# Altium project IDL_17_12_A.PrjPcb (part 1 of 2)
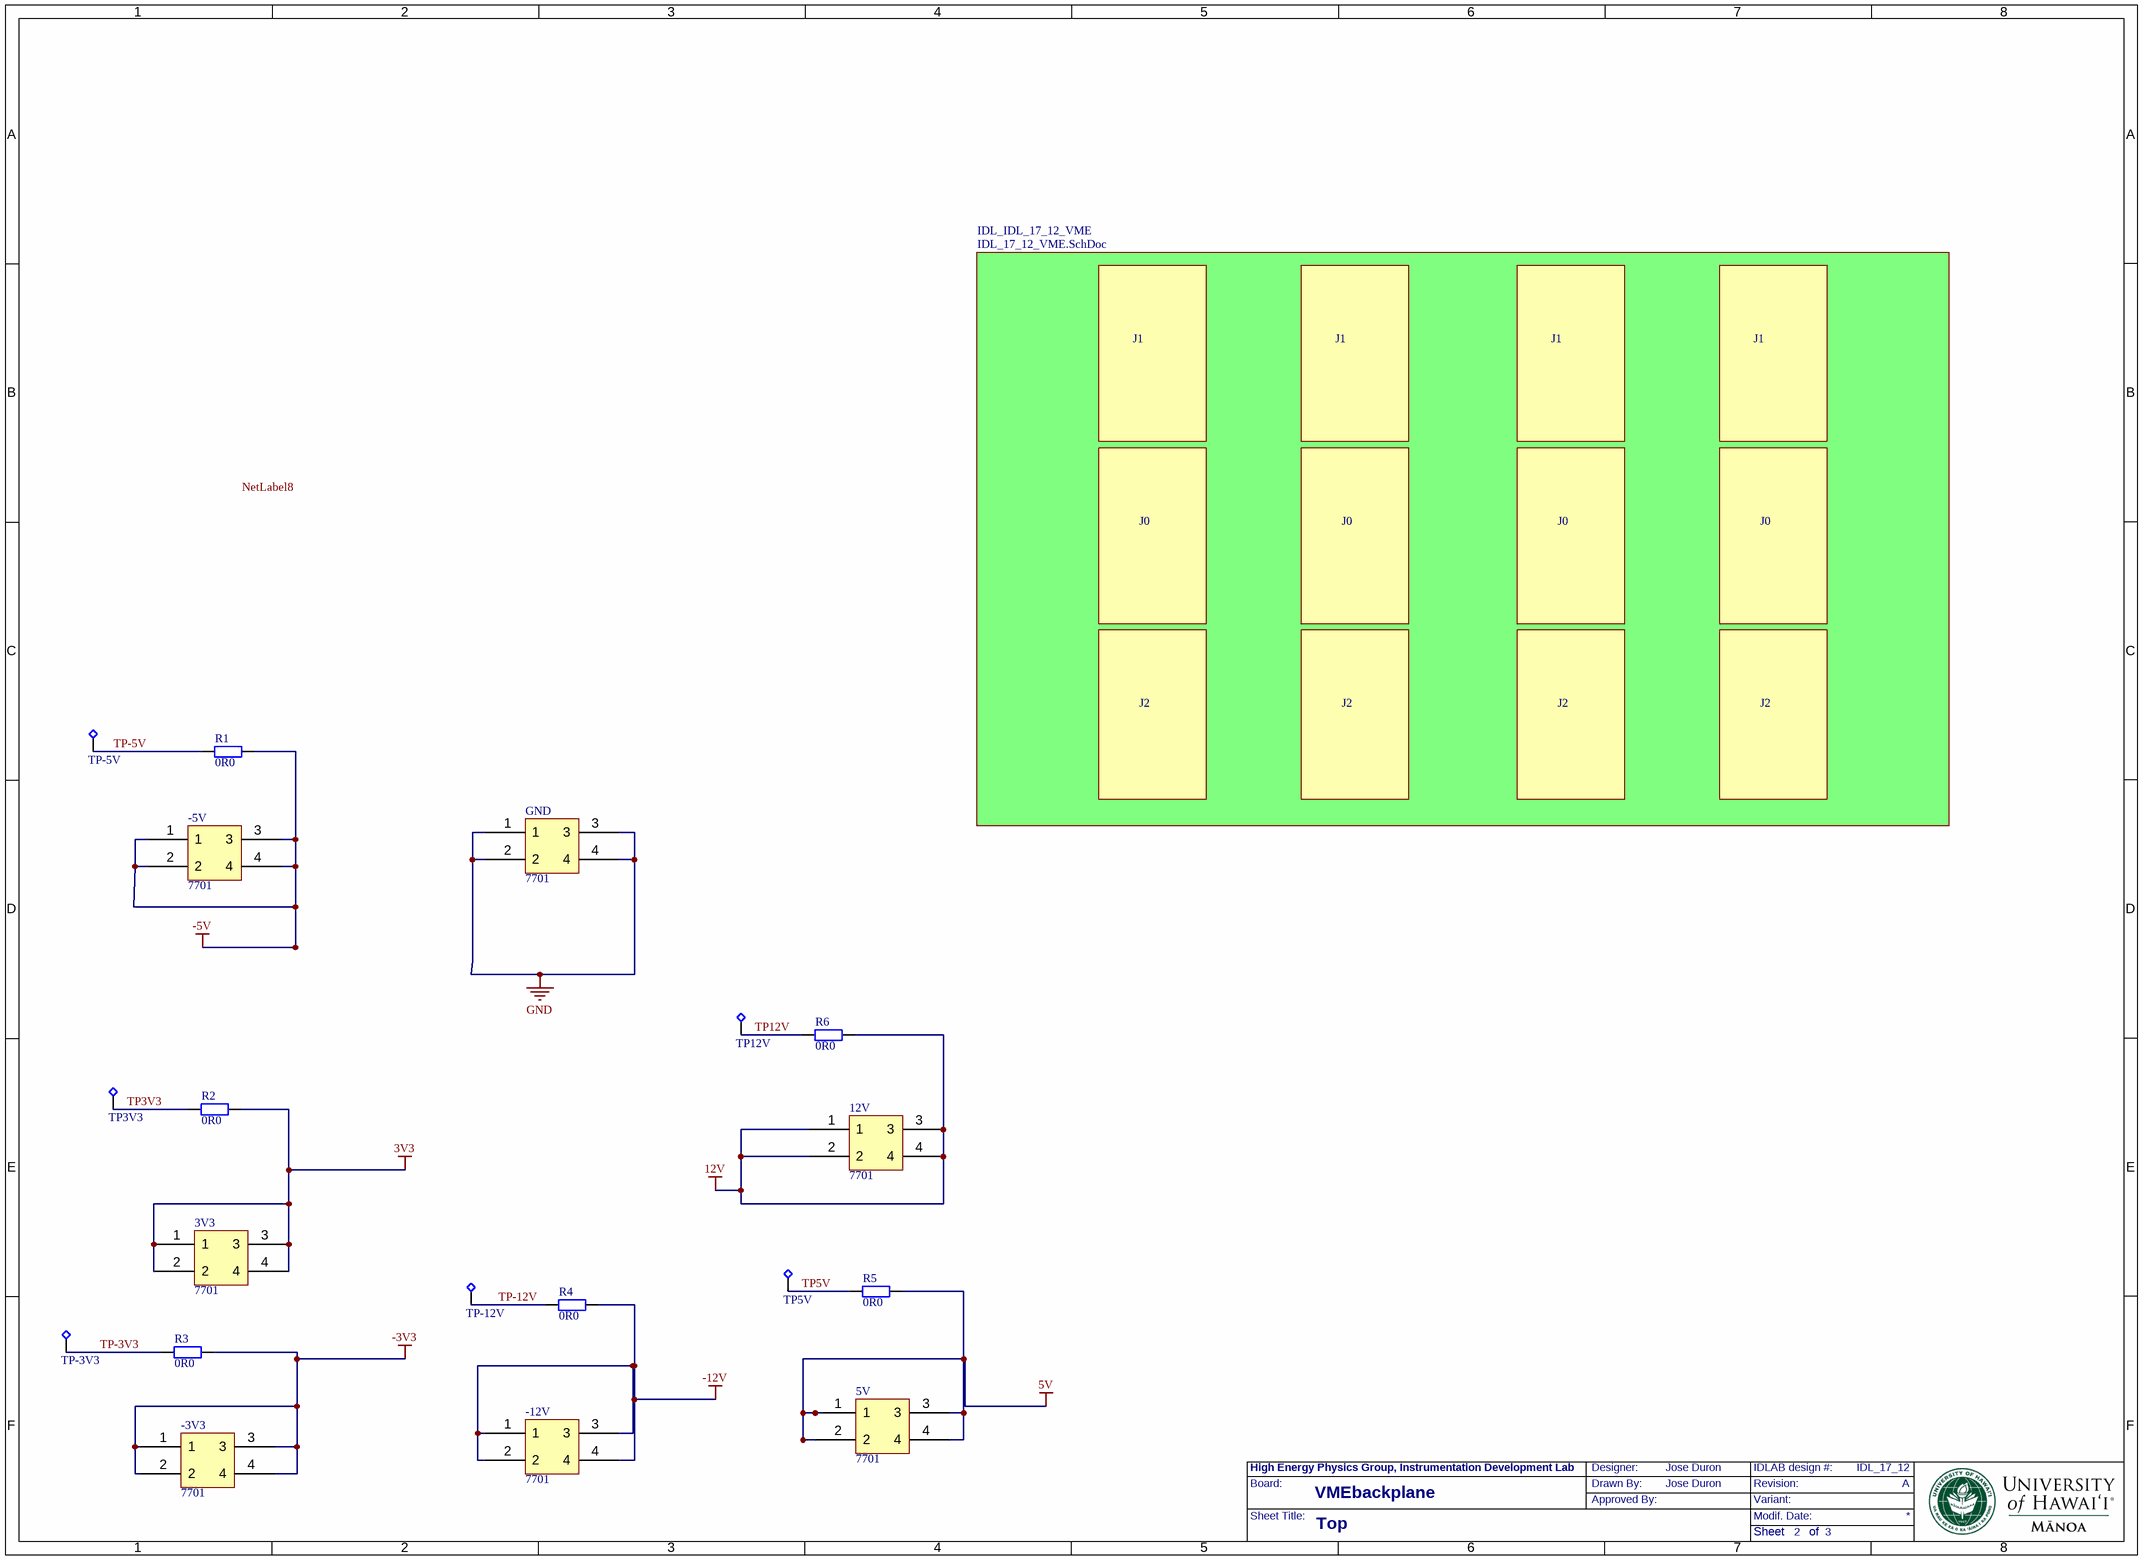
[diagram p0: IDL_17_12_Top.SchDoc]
BoardName: VMEbackplane; Designer: Jose Duron; Drawn_By: Jose Duron; IDLnum: IDL_17_12; ProjectName1: VMEBackplane; RevNum: A
8 sheets, 322 parts. Net scope: flat (ports and power ports of the same name join across sheets).
Board files: IDL_17_12_A.PcbDoc, IDL_17_12_A_pnl.PcbDoc, IDL_17_12_A2.PcbDoc, IDL_17_12_A4.PcbDoc
Sheets:
  PRJHdr_IDL_17_12_A.SchDoc
  IDL_17_12_Top.SchDoc
    IDL_IDL_17_12_VME = IDL_17_12_VME.SchDoc
      IDL_17_12_J1 = IDL_17_12_J1.SchDoc
      IDL_17_12_J2 = IDL_17_12_J2.SchDoc
      IDL_17_12_TerA1 = IDL_17_12_TerA.SchDoc
      IDL_17_12_TerA2 = IDL_17_12_TerA.SchDoc
      IDL_17_12_TerA3 = IDL_17_12_TerA.SchDoc
      IDL_17_12_TerA4 = IDL_17_12_TerA.SchDoc
      IDL_17_12_TerA5 = IDL_17_12_TerA.SchDoc
      IDL_17_12_TerA6 = IDL_17_12_TerA.SchDoc
      IDL_17_12_TerA7 = IDL_17_12_TerA.SchDoc
      IDL_17_12_TerA8 = IDL_17_12_TerA.SchDoc
      IDL_17_12_TerA9 = IDL_17_12_TerA.SchDoc
      IDL_17_12_TerA10 = IDL_17_12_TerA.SchDoc
      IDL_17_12_TerA11 = IDL_17_12_TerA.SchDoc
      IDL_17_12_TerA12 = IDL_17_12_TerA.SchDoc
      IDL_17_12_TerA13 = IDL_17_12_TerA.SchDoc
      IDL_17_12_TerA14 = IDL_17_12_TerA.SchDoc
      IDL_17_12_TerA15 = IDL_17_12_TerA.SchDoc
      IDL_17_12_TerA16 = IDL_17_12_TerA.SchDoc
      IDL_17_12_TerA17 = IDL_17_12_TerA.SchDoc
      IDL_17_12_TerA18 = IDL_17_12_TerA.SchDoc
      IDL_17_12_TerA19 = IDL_17_12_TerA.SchDoc
      IDL_17_12_TerA20 = IDL_17_12_TerA.SchDoc
      IDL_17_12_TerA21 = IDL_17_12_TerA.SchDoc
      IDL_17_12_TerA22 = IDL_17_12_TerA.SchDoc
      IDL_17_12_TerA23 = IDL_17_12_TerA.SchDoc
      IDL_17_12_TerA24 = IDL_17_12_TerA.SchDoc
      IDL_17_12_TerA25 = IDL_17_12_TerA.SchDoc
      IDL_17_12_TerA26 = IDL_17_12_TerA.SchDoc
      IDL_17_12_TerA27 = IDL_17_12_TerA.SchDoc
      IDL_17_12_TerA28 = IDL_17_12_TerA.SchDoc
      IDL_17_12_TerA29 = IDL_17_12_TerA.SchDoc
      IDL_17_12_TerA30 = IDL_17_12_TerA.SchDoc
      IDL_17_12_TerA31 = IDL_17_12_TerA.SchDoc
      IDL_17_12_TerA32 = IDL_17_12_TerA.SchDoc
      IDL_17_12_TerA33 = IDL_17_12_TerA.SchDoc
      IDL_17_12_TerA34 = IDL_17_12_TerA.SchDoc
      IDL_17_12_TerA35 = IDL_17_12_TerA.SchDoc
      IDL_17_12_TerA36 = IDL_17_12_TerA.SchDoc
      IDL_17_12_TerA37 = IDL_17_12_TerA.SchDoc
      IDL_17_12_TerA38 = IDL_17_12_TerA.SchDoc
      IDL_17_12_TerA39 = IDL_17_12_TerA.SchDoc
      IDL_17_12_TerA40 = IDL_17_12_TerA.SchDoc
      IDL_17_12_TerA41 = IDL_17_12_TerA.SchDoc
      IDL_17_12_TerA42 = IDL_17_12_TerA.SchDoc
      IDL_17_12_TerA43 = IDL_17_12_TerA.SchDoc
      IDL_17_12_TerA44 = IDL_17_12_TerA.SchDoc
      IDL_17_12_TerA45 = IDL_17_12_TerA.SchDoc
      IDL_17_12_TerA46 = IDL_17_12_TerA.SchDoc
      IDL_17_12_TerA47 = IDL_17_12_TerA.SchDoc
      IDL_17_12_TerA48 = IDL_17_12_TerA.SchDoc
      IDL_17_12_TerA49 = IDL_17_12_TerA.SchDoc
      IDL_17_12_TerA50 = IDL_17_12_TerA.SchDoc
      IDL_17_12_TerA51 = IDL_17_12_TerA.SchDoc
      IDL_17_12_TerA52 = IDL_17_12_TerA.SchDoc
      IDL_17_12_TerA53 = IDL_17_12_TerA.SchDoc
      IDL_17_12_TerA54 = IDL_17_12_TerA.SchDoc
      IDL_17_12_TerA55 = IDL_17_12_TerA.SchDoc
      IDL_17_12_TerA56 = IDL_17_12_TerA.SchDoc
      IDL_17_12_TerA57 = IDL_17_12_TerA.SchDoc
      IDL_17_12_TerA58 = IDL_17_12_TerA.SchDoc
      IDL_17_12_TerA59 = IDL_17_12_TerA.SchDoc
      IDL_17_12_TerA60 = IDL_17_12_TerA.SchDoc
      IDL_17_12_TerA61 = IDL_17_12_TerA.SchDoc
      IDL_17_12_TerA62 = IDL_17_12_TerA.SchDoc
      IDL_17_12_TerA63 = IDL_17_12_TerA.SchDoc
      IDL_17_12_TerA64 = IDL_17_12_TerA.SchDoc
      IDL_17_12_TerA65 = IDL_17_12_TerA.SchDoc
      IDL_17_12_TerA66 = IDL_17_12_TerA.SchDoc
      IDL_17_12_TerA67 = IDL_17_12_TerA.SchDoc
      IDL_17_12_TerA68 = IDL_17_12_TerA.SchDoc
      IDL_17_12_TerA69 = IDL_17_12_TerA.SchDoc
      IDL_17_12_TerA70 = IDL_17_12_TerA.SchDoc
      IDL_17_12_TerA71 = IDL_17_12_TerA.SchDoc
      IDL_17_12_TerA72 = IDL_17_12_TerA.SchDoc
      IDL_17_12_TerB1 = IDL_17_12_TerB.SchDoc
      IDL_17_12_TerB2 = IDL_17_12_TerB.SchDoc
      IDL_17_12_TerB3 = IDL_17_12_TerB.SchDoc
      IDL_17_12_TerB4 = IDL_17_12_TerB.SchDoc
      IDL_17_12_TerB5 = IDL_17_12_TerB.SchDoc
      IDL_17_12_TerB6 = IDL_17_12_TerB.SchDoc
      IDL_17_12_TerB7 = IDL_17_12_TerB.SchDoc
      IDL_17_12_TerB8 = IDL_17_12_TerB.SchDoc
      IDL_17_12_TerB9 = IDL_17_12_TerB.SchDoc
      IDL_17_12_TerB10 = IDL_17_12_TerB.SchDoc
      IDL_17_12_TerB11 = IDL_17_12_TerB.SchDoc
      IDL_17_12_TerB12 = IDL_17_12_TerB.SchDoc
      IDL_17_12_TerB13 = IDL_17_12_TerB.SchDoc
      IDL_17_12_TerB14 = IDL_17_12_TerB.SchDoc
      IDL_17_12_TerB15 = IDL_17_12_TerB.SchDoc
      IDL_17_12_TerB16 = IDL_17_12_TerB.SchDoc
      IDL_17_12_TerB17 = IDL_17_12_TerB.SchDoc
      IDL_17_12_TerB18 = IDL_17_12_TerB.SchDoc
      IDL_17_12_TerB19 = IDL_17_12_TerB.SchDoc
      IDL_17_12_TerB20 = IDL_17_12_TerB.SchDoc
      IDL_17_12_TerB21 = IDL_17_12_TerB.SchDoc
      IDL_17_12_TerB22 = IDL_17_12_TerB.SchDoc
      IDL_17_12_TerB23 = IDL_17_12_TerB.SchDoc
      IDL_17_12_TerB24 = IDL_17_12_TerB.SchDoc
      IDL_17_12_TerB25 = IDL_17_12_TerB.SchDoc
      IDL_17_12_J0 = IDL_17_12_J0.SchDoc

## Sheet PRJHdr_IDL_17_12_A.SchDoc: Title_doc_parameter!
size 401 x 291 mm; DocumentNumber: 1; SheetNumber: 1; SheetTotal: 3; Project_IT-Code: XXXX

## Sheet IDL_17_12_Top.SchDoc: Top
size 401 x 291 mm; DocumentNumber: 2; SheetNumber: 2; SheetTotal: 3

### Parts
3V3  7701  [PCBComponent_1]
5V  7701  [PCBComponent_1]
12V  7701  [PCBComponent_1]
-3V3  7701  [PCBComponent_1]
-5V  7701  [PCBComponent_1]
-12V  7701  [PCBComponent_1]
GND  7701  [PCBComponent_1]
R1  0R0  [RC0402N1R]
R2  0R0  [RC0402N1R]
R3  0R0  [RC0402N1R]
R4  0R0  [RC0402N1R]
R5  0R0  [RC0402N1R]
R6  0R0  [RC0402N1R]
TP3V3  TP 0.5mm  [TPH0.5S]  (value not drawn)  (no BOM)
TP5V  TP 0.5mm  [TPH0.5S]  (value not drawn)  (no BOM)
TP12V  TP 0.5mm  [TPH0.5S]  (value not drawn)  (no BOM)
TP-3V3  TP 0.5mm  [TPH0.5S]  (value not drawn)  (no BOM)
TP-5V  TP 0.5mm  [TPH0.5S]  (value not drawn)  (no BOM)
TP-12V  TP 0.5mm  [TPH0.5S]  (value not drawn)  (no BOM)

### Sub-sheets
IDL_IDL_17_12_VME = IDL_17_12_VME.SchDoc: no entries

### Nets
3V3: 3V3.1 3V3.2 3V3.3 3V3.4 R2.2
5V: 5V.1 5V.2 5V.3 5V.4 R5.2
12V: 12V.1 12V.2 12V.3 12V.4 R6.2
-3V3: -3V3.1 -3V3.2 -3V3.3 -3V3.4 R3.2
-5V: -5V.1 -5V.2 -5V.3 -5V.4 R1.2
-12V: -12V.1 -12V.2 -12V.3 -12V.4 R4.2
GND: GND.1 GND.2 GND.3 GND.4
TP3V3: R2.1 TP3V3.1  [project net TP3V3_2]
TP5V: R5.1 TP5V.1  [project net TP5V_2]
TP12V: R6.1 TP12V.1  [project net TP12V_2]
TP-3V3: R3.1 TP-3V3.1  [project net TP-3V3_2]
TP-5V: R1.1 TP-5V.1  [project net TP-5V_2]
TP-12V: R4.1 TP-12V.1  [project net TP-12V_2]

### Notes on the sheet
- J1
- J0
- J2
- Labels drawn without touching a wire or pin: NetLabel8

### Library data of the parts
3V3 5V 12V -3V3 -5V -12V GND = Component_1: TERM SCREW 6-32 4 PIN PCB
R1-R6 = RES0402-0-0R-1%100PPM: Chip Resistor 0402 62.5mW 1% 100ppm; Manufacturer: Panasonic; Manufacturer No: ERJ-2GE0R00X; Tech: SMDR
TP3V3 TP5V TP12V TP-3V3 TP-5V TP-12V = ELE-TP0.5S: Test Point 0.5mm Slim; Sort: 610; Tech: THDW

## Sheet IDL_17_12_VME.SchDoc: VME
size 401 x 291 mm; SheetNumber: 3
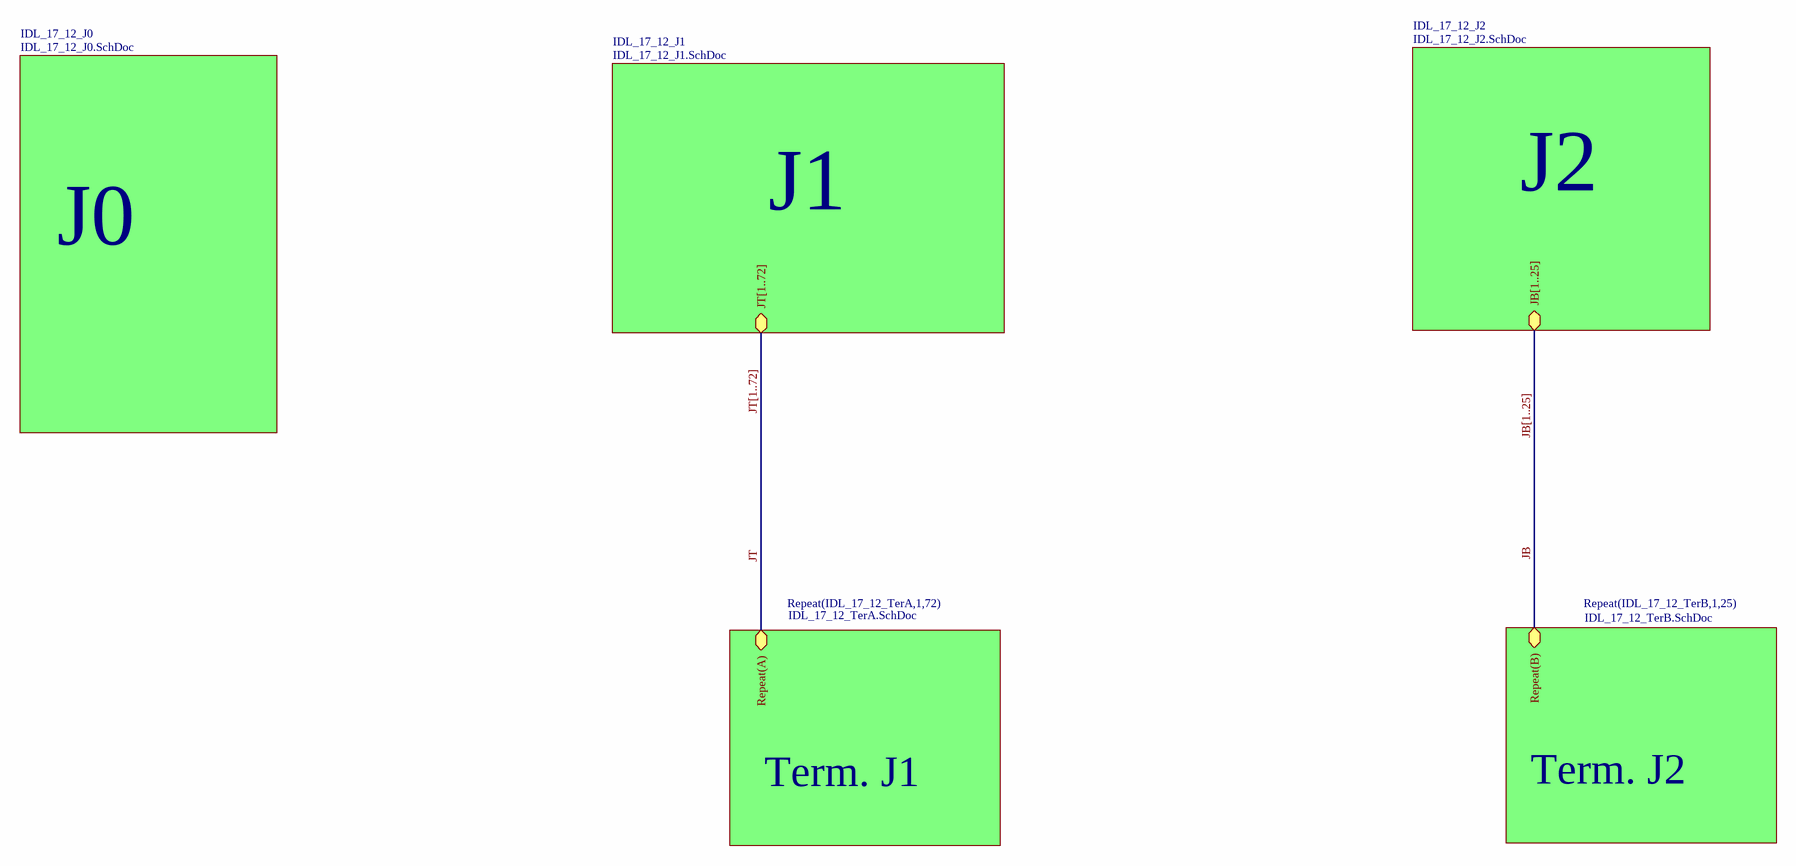
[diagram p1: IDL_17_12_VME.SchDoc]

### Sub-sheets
IDL_17_12_J0 = IDL_17_12_J0.SchDoc: no entries
IDL_17_12_J1 = IDL_17_12_J1.SchDoc: JT[1..72]
IDL_17_12_J2 = IDL_17_12_J2.SchDoc: JB[1..25]
Repeat(IDL_17_12_TerA,1,72) = IDL_17_12_TerA.SchDoc: Repeat(A)
Repeat(IDL_17_12_TerB,1,25) = IDL_17_12_TerB.SchDoc: Repeat(B)

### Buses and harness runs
bus JB[1..25] = sheet IDL_17_12_J2/JB[1..25]
bus JT[1..72] = sheet IDL_17_12_J1/JT[1..72]

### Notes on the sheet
- J1
- J2
- J0
- Term. J1
- Term. J2

## Sheet IDL_17_12_J1.SchDoc: J1
size 401 x 291 mm; SheetNumber: 5
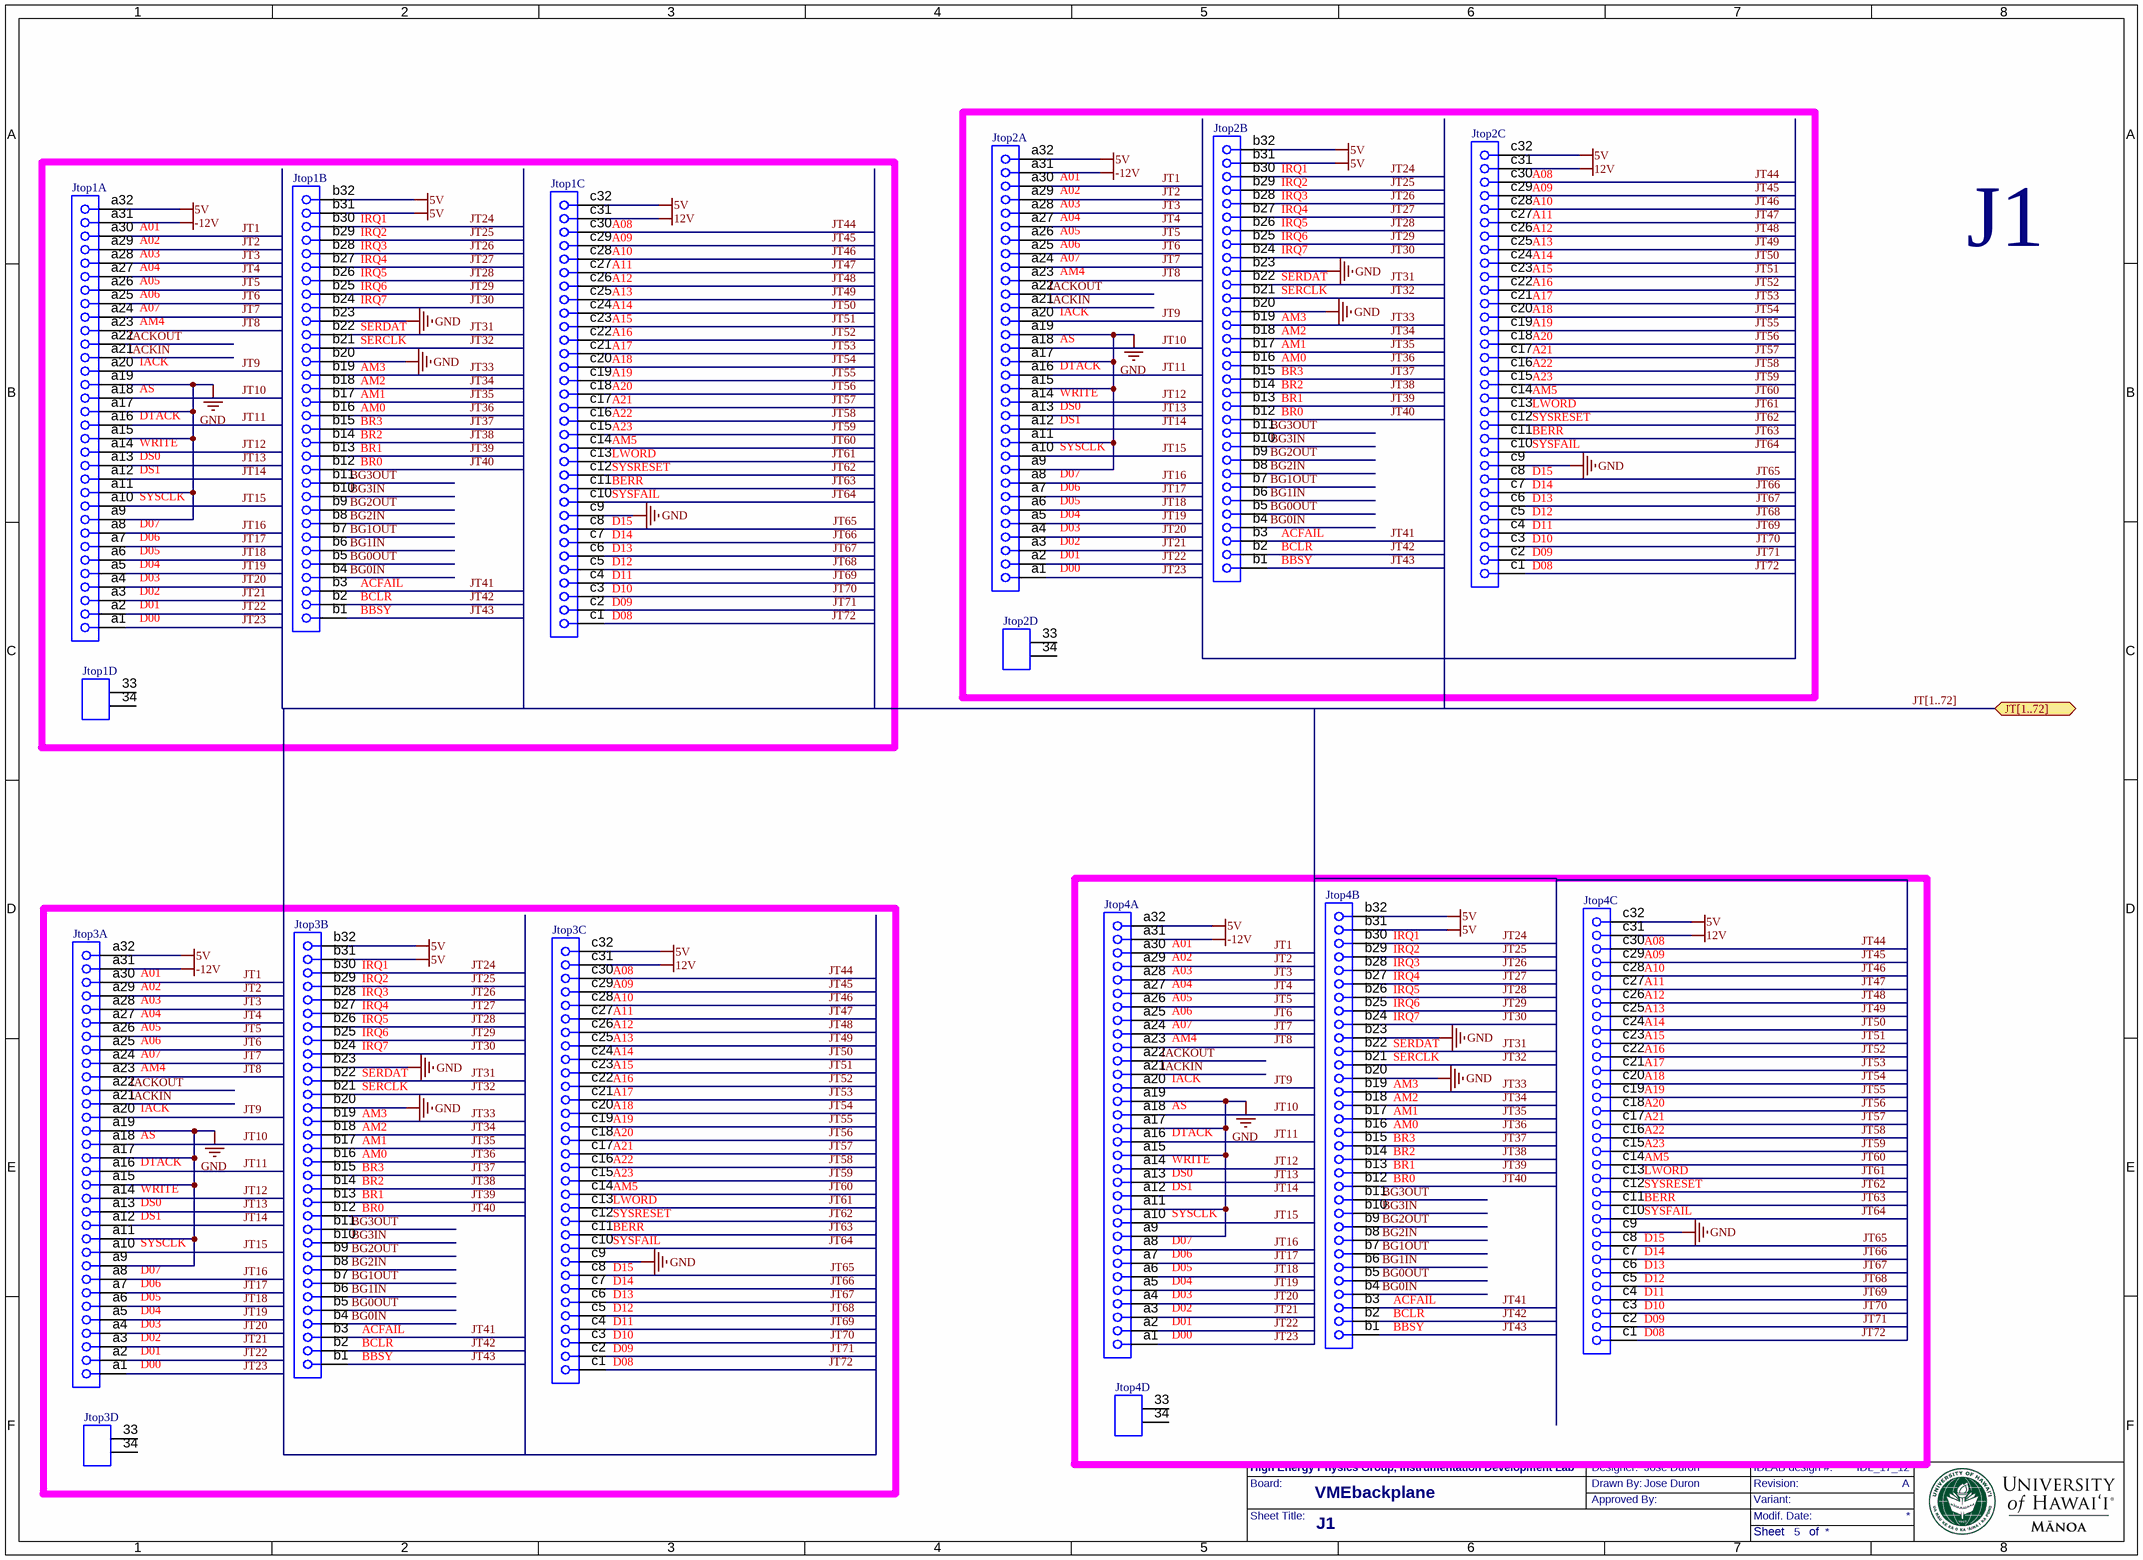
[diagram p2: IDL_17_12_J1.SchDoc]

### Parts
Jtop1  (no value)  [0903296x825]  (parts A,B,C,D of 4)
Jtop2  (no value)  [0903296x825]  (parts A,B,C,D of 4)
Jtop3  (no value)  [0903296x825]  (parts A,B,C,D of 4)
Jtop4  (no value)  [0903296x825]  (parts A,B,C,D of 4)

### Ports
JT[1..72]

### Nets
5V: Jtop1.a32 Jtop1.b31 Jtop1.b32 Jtop1.c32 Jtop2.a32 Jtop2.b31 Jtop2.b32 Jtop2.c32 Jtop3.a32 Jtop3.b31 Jtop3.b32 Jtop3.c32 Jtop4.a32 Jtop4.b31 Jtop4.b32 Jtop4.c32
12V: Jtop1.c31 Jtop2.c31 Jtop3.c31 Jtop4.c31
-12V: Jtop1.a31 Jtop2.a31 Jtop3.a31 Jtop4.a31
GND: Jtop1.a9 Jtop1.a11 Jtop1.a15 Jtop1.a17 Jtop1.a19 Jtop1.b20 Jtop1.b23 Jtop1.c9 Jtop2.a9 Jtop2.a11 Jtop2.a15 Jtop2.a17 Jtop2.a19 Jtop2.b20 Jtop2.b23 Jtop2.c9 Jtop3.a9 Jtop3.a11 Jtop3.a15 Jtop3.a17 Jtop3.a19 Jtop3.b20 Jtop3.b23 Jtop3.c9 Jtop4.a9 Jtop4.a11 Jtop4.a15 Jtop4.a17 Jtop4.a19 Jtop4.b20 Jtop4.b23 Jtop4.c9
BG0IN: Jtop1.b4 Jtop2.b4 Jtop3.b4 Jtop4.b4  [project net BG0IN_5]
BG0OUT: Jtop1.b5 Jtop2.b5 Jtop3.b5 Jtop4.b5  [project net BG0OUT_5]
BG1IN: Jtop1.b6 Jtop2.b6 Jtop3.b6 Jtop4.b6  [project net BG1IN_5]
BG1OUT: Jtop1.b7 Jtop2.b7 Jtop3.b7 Jtop4.b7  [project net BG1OUT_5]
BG2IN: Jtop1.b8 Jtop2.b8 Jtop3.b8 Jtop4.b8  [project net BG2IN_5]
BG2OUT: Jtop1.b9 Jtop2.b9 Jtop3.b9 Jtop4.b9  [project net BG2OUT_5]
BG3IN: Jtop1.b10 Jtop2.b10 Jtop3.b10 Jtop4.b10  [project net BG3IN_5]
BG3OUT: Jtop1.b11 Jtop2.b11 Jtop3.b11 Jtop4.b11  [project net BG3OUT_5]
IACKIN: Jtop1.a21 Jtop2.a21 Jtop3.a21 Jtop4.a21  [project net IACKIN_5]
IACKOUT: Jtop1.a22 Jtop2.a22 Jtop3.a22 Jtop4.a22  [project net IACKOUT_5]
JT1: Jtop1.a30 Jtop2.a30 Jtop3.a30 Jtop4.a30  [project net JT1_5]
JT2: Jtop1.a29 Jtop2.a29 Jtop3.a29 Jtop4.a29  [project net JT2_5]
JT3: Jtop1.a28 Jtop2.a28 Jtop3.a28 Jtop4.a28  [project net JT3_5]
JT4: Jtop1.a27 Jtop2.a27 Jtop3.a27 Jtop4.a27  [project net JT4_5]
JT5: Jtop1.a26 Jtop2.a26 Jtop3.a26 Jtop4.a26  [project net JT5_5]
JT6: Jtop1.a25 Jtop2.a25 Jtop3.a25 Jtop4.a25  [project net JT6_5]
JT7: Jtop1.a24 Jtop2.a24 Jtop3.a24 Jtop4.a24  [project net JT7_5]
JT8: Jtop1.a23 Jtop2.a23 Jtop3.a23 Jtop4.a23  [project net JT8_5]
JT9: Jtop1.a20 Jtop2.a20 Jtop3.a20 Jtop4.a20  [project net JT9_5]
JT10: Jtop1.a18 Jtop2.a18 Jtop3.a18 Jtop4.a18  [project net JT10_5]
JT11: Jtop1.a16 Jtop2.a16 Jtop3.a16 Jtop4.a16  [project net JT11_5]
JT12: Jtop1.a14 Jtop2.a14 Jtop3.a14 Jtop4.a14  [project net JT12_5]
JT13: Jtop1.a13 Jtop2.a13 Jtop3.a13 Jtop4.a13  [project net JT13_5]
JT14: Jtop1.a12 Jtop2.a12 Jtop3.a12 Jtop4.a12  [project net JT14_5]
JT15: Jtop1.a10 Jtop2.a10 Jtop3.a10 Jtop4.a10  [project net JT15_5]
JT16: Jtop1.a8 Jtop2.a8 Jtop3.a8 Jtop4.a8  [project net JT16_5]
JT17: Jtop1.a7 Jtop2.a7 Jtop3.a7 Jtop4.a7  [project net JT17_5]
JT18: Jtop1.a6 Jtop2.a6 Jtop3.a6 Jtop4.a6  [project net JT18_5]
JT19: Jtop1.a5 Jtop2.a5 Jtop3.a5 Jtop4.a5  [project net JT19_5]
JT20: Jtop1.a4 Jtop2.a4 Jtop3.a4 Jtop4.a4  [project net JT20_5]
JT21: Jtop1.a3 Jtop2.a3 Jtop3.a3 Jtop4.a3  [project net JT21_5]
JT22: Jtop1.a2 Jtop2.a2 Jtop3.a2 Jtop4.a2  [project net JT22_5]
JT23: Jtop1.a1 Jtop2.a1 Jtop3.a1 Jtop4.a1  [project net JT23_5]
JT24: Jtop1.b30 Jtop2.b30 Jtop3.b30 Jtop4.b30  [project net JT24_5]
JT25: Jtop1.b29 Jtop2.b29 Jtop3.b29 Jtop4.b29  [project net JT25_5]
JT26: Jtop1.b28 Jtop2.b28 Jtop3.b28 Jtop4.b28  [project net JT26_5]
JT27: Jtop1.b27 Jtop2.b27 Jtop3.b27 Jtop4.b27  [project net JT27_5]
JT28: Jtop1.b26 Jtop2.b26 Jtop3.b26 Jtop4.b26  [project net JT28_5]
JT29: Jtop1.b25 Jtop2.b25 Jtop3.b25 Jtop4.b25  [project net JT29_5]
JT30: Jtop1.b24 Jtop2.b24 Jtop3.b24 Jtop4.b24  [project net JT30_5]
JT31: Jtop1.b22 Jtop2.b22 Jtop3.b22 Jtop4.b22  [project net JT31_5]
JT32: Jtop1.b21 Jtop2.b21 Jtop3.b21 Jtop4.b21  [project net JT32_5]
JT33: Jtop1.b19 Jtop2.b19 Jtop3.b19 Jtop4.b19  [project net JT33_5]
JT34: Jtop1.b18 Jtop2.b18 Jtop3.b18 Jtop4.b18  [project net JT34_5]
JT35: Jtop1.b17 Jtop2.b17 Jtop3.b17 Jtop4.b17  [project net JT35_5]
JT36: Jtop1.b16 Jtop2.b16 Jtop3.b16 Jtop4.b16  [project net JT36_5]
JT37: Jtop1.b15 Jtop2.b15 Jtop3.b15 Jtop4.b15  [project net JT37_5]
JT38: Jtop1.b14 Jtop2.b14 Jtop3.b14 Jtop4.b14  [project net JT38_5]
JT39: Jtop1.b13 Jtop2.b13 Jtop3.b13 Jtop4.b13  [project net JT39_5]
JT40: Jtop1.b12 Jtop2.b12 Jtop3.b12 Jtop4.b12  [project net JT40_5]
JT41: Jtop1.b3 Jtop2.b3 Jtop3.b3 Jtop4.b3  [project net JT41_5]
JT42: Jtop1.b2 Jtop2.b2 Jtop3.b2 Jtop4.b2  [project net JT42_5]
JT43: Jtop1.b1 Jtop2.b1 Jtop3.b1 Jtop4.b1  [project net JT43_5]
JT44: Jtop1.c30 Jtop2.c30 Jtop3.c30 Jtop4.c30  [project net JT44_5]
JT45: Jtop1.c29 Jtop2.c29 Jtop3.c29 Jtop4.c29  [project net JT45_5]
JT46: Jtop1.c28 Jtop2.c28 Jtop3.c28 Jtop4.c28  [project net JT46_5]
JT47: Jtop1.c27 Jtop2.c27 Jtop3.c27 Jtop4.c27  [project net JT47_5]
JT48: Jtop1.c26 Jtop2.c26 Jtop3.c26 Jtop4.c26  [project net JT48_5]
JT49: Jtop1.c25 Jtop2.c25 Jtop3.c25 Jtop4.c25  [project net JT49_5]
JT50: Jtop1.c24 Jtop2.c24 Jtop3.c24 Jtop4.c24  [project net JT50_5]
JT51: Jtop1.c23 Jtop2.c23 Jtop3.c23 Jtop4.c23  [project net JT51_5]
JT52: Jtop1.c22 Jtop2.c22 Jtop3.c22 Jtop4.c22  [project net JT52_5]
JT53: Jtop1.c21 Jtop2.c21 Jtop3.c21 Jtop4.c21  [project net JT53_5]
JT54: Jtop1.c20 Jtop2.c20 Jtop3.c20 Jtop4.c20  [project net JT54_5]
JT55: Jtop1.c19 Jtop2.c19 Jtop3.c19 Jtop4.c19  [project net JT55_5]
JT56: Jtop1.c18 Jtop2.c18 Jtop3.c18 Jtop4.c18  [project net JT56_5]
JT57: Jtop1.c17 Jtop2.c17 Jtop3.c17 Jtop4.c17  [project net JT57_5]
JT58: Jtop1.c16 Jtop2.c16 Jtop3.c16 Jtop4.c16  [project net JT58_5]
JT59: Jtop1.c15 Jtop2.c15 Jtop3.c15 Jtop4.c15  [project net JT59_5]
JT60: Jtop1.c14 Jtop2.c14 Jtop3.c14 Jtop4.c14  [project net JT60_5]
JT61: Jtop1.c13 Jtop2.c13 Jtop3.c13 Jtop4.c13  [project net JT61_5]
JT62: Jtop1.c12 Jtop2.c12 Jtop3.c12 Jtop4.c12  [project net JT62_5]
JT63: Jtop1.c11 Jtop2.c11 Jtop3.c11 Jtop4.c11  [project net JT63_5]
JT64: Jtop1.c10 Jtop2.c10 Jtop3.c10 Jtop4.c10  [project net JT64_5]
JT65: Jtop1.c8 Jtop2.c8 Jtop3.c8 Jtop4.c8  [project net JT65_5]
JT66: Jtop1.c7 Jtop2.c7 Jtop3.c7 Jtop4.c7  [project net JT66_5]
JT67: Jtop1.c6 Jtop2.c6 Jtop3.c6 Jtop4.c6  [project net JT67_5]
JT68: Jtop1.c5 Jtop2.c5 Jtop3.c5 Jtop4.c5  [project net JT68_5]
JT69: Jtop1.c4 Jtop2.c4 Jtop3.c4 Jtop4.c4  [project net JT69_5]
JT70: Jtop1.c3 Jtop2.c3 Jtop3.c3 Jtop4.c3  [project net JT70_5]
JT71: Jtop1.c2 Jtop2.c2 Jtop3.c2 Jtop4.c2  [project net JT71_5]
JT72: Jtop1.c1 Jtop2.c1 Jtop3.c1 Jtop4.c1  [project net JT72_5]

Not connected (* = marked no-connect by the designer): Jtop1 33(MH1) 34(MH2); Jtop2 33(MH1) 34(MH2); Jtop3 33(MH1) 34(MH2); Jtop4 33(MH1) 34(MH2)

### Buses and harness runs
bus JT[1..72] = port JT[1..72]

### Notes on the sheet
- (near Jtop1) A01
- (near Jtop1) IRQ1
- (near Jtop1) A08
- (near Jtop2) A01
- (near Jtop2) A02
- (near Jtop2) A03
- (near Jtop2) A04
- (near Jtop2) A05
- (near Jtop2) IRQ1
- (near Jtop2) IRQ2
- (near Jtop2) IRQ3
- (near Jtop2) IRQ4
- (near Jtop2) IRQ5
- (near Jtop2) A08
- (near Jtop2) A09
- (near Jtop2) A10
- (near Jtop2) A11
- (near Jtop2) A12
- (near Jtop1) A02
- (near Jtop1) A03
- (near Jtop1) A04
- (near Jtop1) A05
- (near Jtop1) A06
- (near Jtop1) IRQ2
- (near Jtop1) IRQ3
- (near Jtop1) IRQ4
- (near Jtop1) IRQ5
- (near Jtop1) IRQ6
- (near Jtop1) A09
- (near Jtop1) A10
- (near Jtop1) A11
- (near Jtop1) A12
- (near Jtop1) A13
- (near Jtop2) A06
- (near Jtop2) A07
- (near Jtop2) AM4
- (near Jtop2) IRQ6
- (near Jtop2) IRQ7
- (near Jtop2) SERDAT
- (near Jtop2) SERCLK
- (near Jtop2) A13
- (near Jtop2) A14
- (near Jtop2) A15
- (near Jtop2) A16
- (near Jtop2) A17
- J1
- (near Jtop1) A07
- (near Jtop1) AM4
- (near Jtop1) IACK
- (near Jtop1) IRQ7
- (near Jtop1) SERDAT
- (near Jtop1) SERCLK
- (near Jtop1) A14
- (near Jtop1) A15
- (near Jtop1) A16
- (near Jtop1) A17
- (near Jtop1) A18
- (near Jtop2) IACK
- (near Jtop2) AS
- (near Jtop2) DTACK
- (near Jtop2) AM3
- (near Jtop2) AM2
- (near Jtop2) AM1
- (near Jtop2) AM0
- (near Jtop2) A18
- (near Jtop2) A19
- (near Jtop2) A20
- (near Jtop2) A21
- (near Jtop2) A22
- (near Jtop1) AS
- (near Jtop1) DTACK
- (near Jtop1) AM3
- (near Jtop1) AM2
- (near Jtop1) AM1
- (near Jtop1) AM0
- (near Jtop1) BR3
- (near Jtop1) A19
- (near Jtop1) A20
- (near Jtop1) A21
- (near Jtop1) A22
- (near Jtop1) A23
- (near Jtop2) WRITE
- (near Jtop2) DS0
- (near Jtop2) DS1
- (near Jtop2) BR3
- (near Jtop2) BR2
- (near Jtop2) BR1
- (near Jtop2) BR0
- (near Jtop2) A23
- (near Jtop2) AM5
- (near Jtop2) LWORD
- (near Jtop2) SYSRESET
- (near Jtop2) BERR
- (near Jtop1) WRITE
- (near Jtop1) DS0
- (near Jtop1) DS1
- (near Jtop1) SYSCLK
- (near Jtop1) BR2
- (near Jtop1) BR1
- (near Jtop1) BR0
- (near Jtop1) AM5
- (near Jtop1) LWORD
- (near Jtop1) SYSRESET
- (near Jtop1) BERR
- (near Jtop1) SYSFAIL
- (near Jtop2) SYSCLK
- (near Jtop2) D07
- (near Jtop2) D06
- (near Jtop2) D05
- (near Jtop2) SYSFAIL
- (near Jtop2) D15
- (near Jtop2) D14
- (near Jtop2) D13
- (near Jtop1) D07
- (near Jtop1) D06
- (near Jtop1) D05
- (near Jtop1) D04
- (near Jtop1) D15
- (near Jtop1) D14
- (near Jtop1) D13
- (near Jtop1) D12
- (near Jtop2) D04
- (near Jtop2) D03
- (near Jtop2) D02
- (near Jtop2) D01
- (near Jtop2) ACFAIL
- (near Jtop2) BCLR
- (near Jtop2) BBSY
- (near Jtop2) D12
- (near Jtop2) D11
- (near Jtop2) D10
- (near Jtop2) D09
- (near Jtop2) D08
- (near Jtop1) D03
- (near Jtop1) D02
- (near Jtop1) D01
- (near Jtop1) D00
- (near Jtop1) ACFAIL
- (near Jtop1) BCLR
- (near Jtop1) BBSY
- (near Jtop1) D11
- (near Jtop1) D10
- (near Jtop1) D09
- (near Jtop1) D08
- (near Jtop2) D00
- (near Jtop3) IRQ1
- (near Jtop3) A08
- (near Jtop4) A01
- (near Jtop4) A02
- (near Jtop4) A03
- (near Jtop4) IRQ1
- (near Jtop4) IRQ2
- (near Jtop4) IRQ3
- (near Jtop4) A08
- (near Jtop4) A09
- (near Jtop4) A10
- (near Jtop3) A01
- (near Jtop3) A02
- (near Jtop3) A03
- (near Jtop3) A04
- (near Jtop3) A05
- (near Jtop3) A06
- (near Jtop3) IRQ2
- (near Jtop3) IRQ3
- (near Jtop3) IRQ4
- (near Jtop3) IRQ5
- (near Jtop3) IRQ6
- (near Jtop3) A09
- (near Jtop3) A10
- (near Jtop3) A11
- (near Jtop3) A12
- (near Jtop3) A13
- (near Jtop4) A04
- (near Jtop4) A05
- (near Jtop4) A06
- (near Jtop4) A07
- (near Jtop4) AM4
- (near Jtop4) IRQ4
- (near Jtop4) IRQ5
- (near Jtop4) IRQ6
- (near Jtop4) IRQ7
- (near Jtop4) A11
- (near Jtop4) A12
- (near Jtop4) A13
- (near Jtop4) A14
- (near Jtop4) A15
- (near Jtop3) A07
- (near Jtop3) AM4
- (near Jtop3) IRQ7
- (near Jtop3) SERDAT
- (near Jtop3) SERCLK
- (near Jtop3) A14
- (near Jtop3) A15
- (near Jtop3) A16
- (near Jtop3) A17
- (near Jtop3) A18
- (near Jtop4) IACK
- (near Jtop4) AS
- (near Jtop4) SERDAT
- (near Jtop4) SERCLK
- (near Jtop4) AM3
- (near Jtop4) AM2
- (near Jtop4) A16
- (near Jtop4) A17
- (near Jtop4) A18
- (near Jtop4) A19
- (near Jtop4) A20
- (near Jtop3) IACK
- (near Jtop3) AS
- (near Jtop3) DTACK
- (near Jtop3) AM3
- (near Jtop3) AM2
- (near Jtop3) AM1
- (near Jtop3) AM0
- (near Jtop3) BR3
- (near Jtop3) A19
- (near Jtop3) A20
- (near Jtop3) A21
- (near Jtop3) A22
- (near Jtop3) A23
- (near Jtop4) DTACK
- (near Jtop4) WRITE
- (near Jtop4) DS0
- (near Jtop4) AM1
- (near Jtop4) AM0
- (near Jtop4) BR3
- (near Jtop4) BR2
- (near Jtop4) BR1
- (near Jtop4) A21
- (near Jtop4) A22
- (near Jtop4) A23
- (near Jtop4) AM5
- (near Jtop4) LWORD
- (near Jtop3) WRITE
- (near Jtop3) DS0
- (near Jtop3) DS1
- (near Jtop3) BR2
- (near Jtop3) BR1
- (near Jtop3) BR0
- (near Jtop3) AM5
- (near Jtop3) LWORD
- (near Jtop3) SYSRESET
- (near Jtop3) BERR
- (near Jtop3) SYSFAIL
- (near Jtop4) DS1
- (near Jtop4) SYSCLK
- (near Jtop4) D07
- (near Jtop4) BR0
- (near Jtop4) SYSRESET
- (near Jtop4) BERR
- (near Jtop4) SYSFAIL
- (near Jtop4) D15
- (near Jtop3) SYSCLK
- (near Jtop3) D07
- (near Jtop3) D06
- (near Jtop3) D05
- (near Jtop3) D04
- (near Jtop3) D15
- (near Jtop3) D14
- (near Jtop3) D13
- (near Jtop3) D12
- (near Jtop4) D06
- (near Jtop4) D05
- (near Jtop4) D04
- (near Jtop4) D03
- (near Jtop4) D02
- (near Jtop4) ACFAIL
- (near Jtop4) D14
- (near Jtop4) D13
- (near Jtop4) D12
- (near Jtop4) D11
- (near Jtop4) D10
- (near Jtop3) D03
- (near Jtop3) D02
- (near Jtop3) D01
- (near Jtop3) D00
- (near Jtop3) ACFAIL
- (near Jtop3) BCLR
- (near Jtop3) BBSY
- (near Jtop3) D11
- (near Jtop3) D10
- (near Jtop3) D09
- (near Jtop3) D08
- (near Jtop4) D01
- (near Jtop4) D00
- (near Jtop4) BCLR
- (near Jtop4) BBSY
- (near Jtop4) D09
- (near Jtop4) D08

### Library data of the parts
Jtop1-Jtop4 = 09 03 296 2825: Eurocard DIN 41612, Type C, 96 Position, Rows a+b+c, Performance level 1, Female, Lead 4.5 mm, Pitch 2.54 mm; DrillSize: Corresponds to nominal value.

## Sheet IDL_17_12_J2.SchDoc: J2
size 401 x 291 mm; SheetNumber: 6
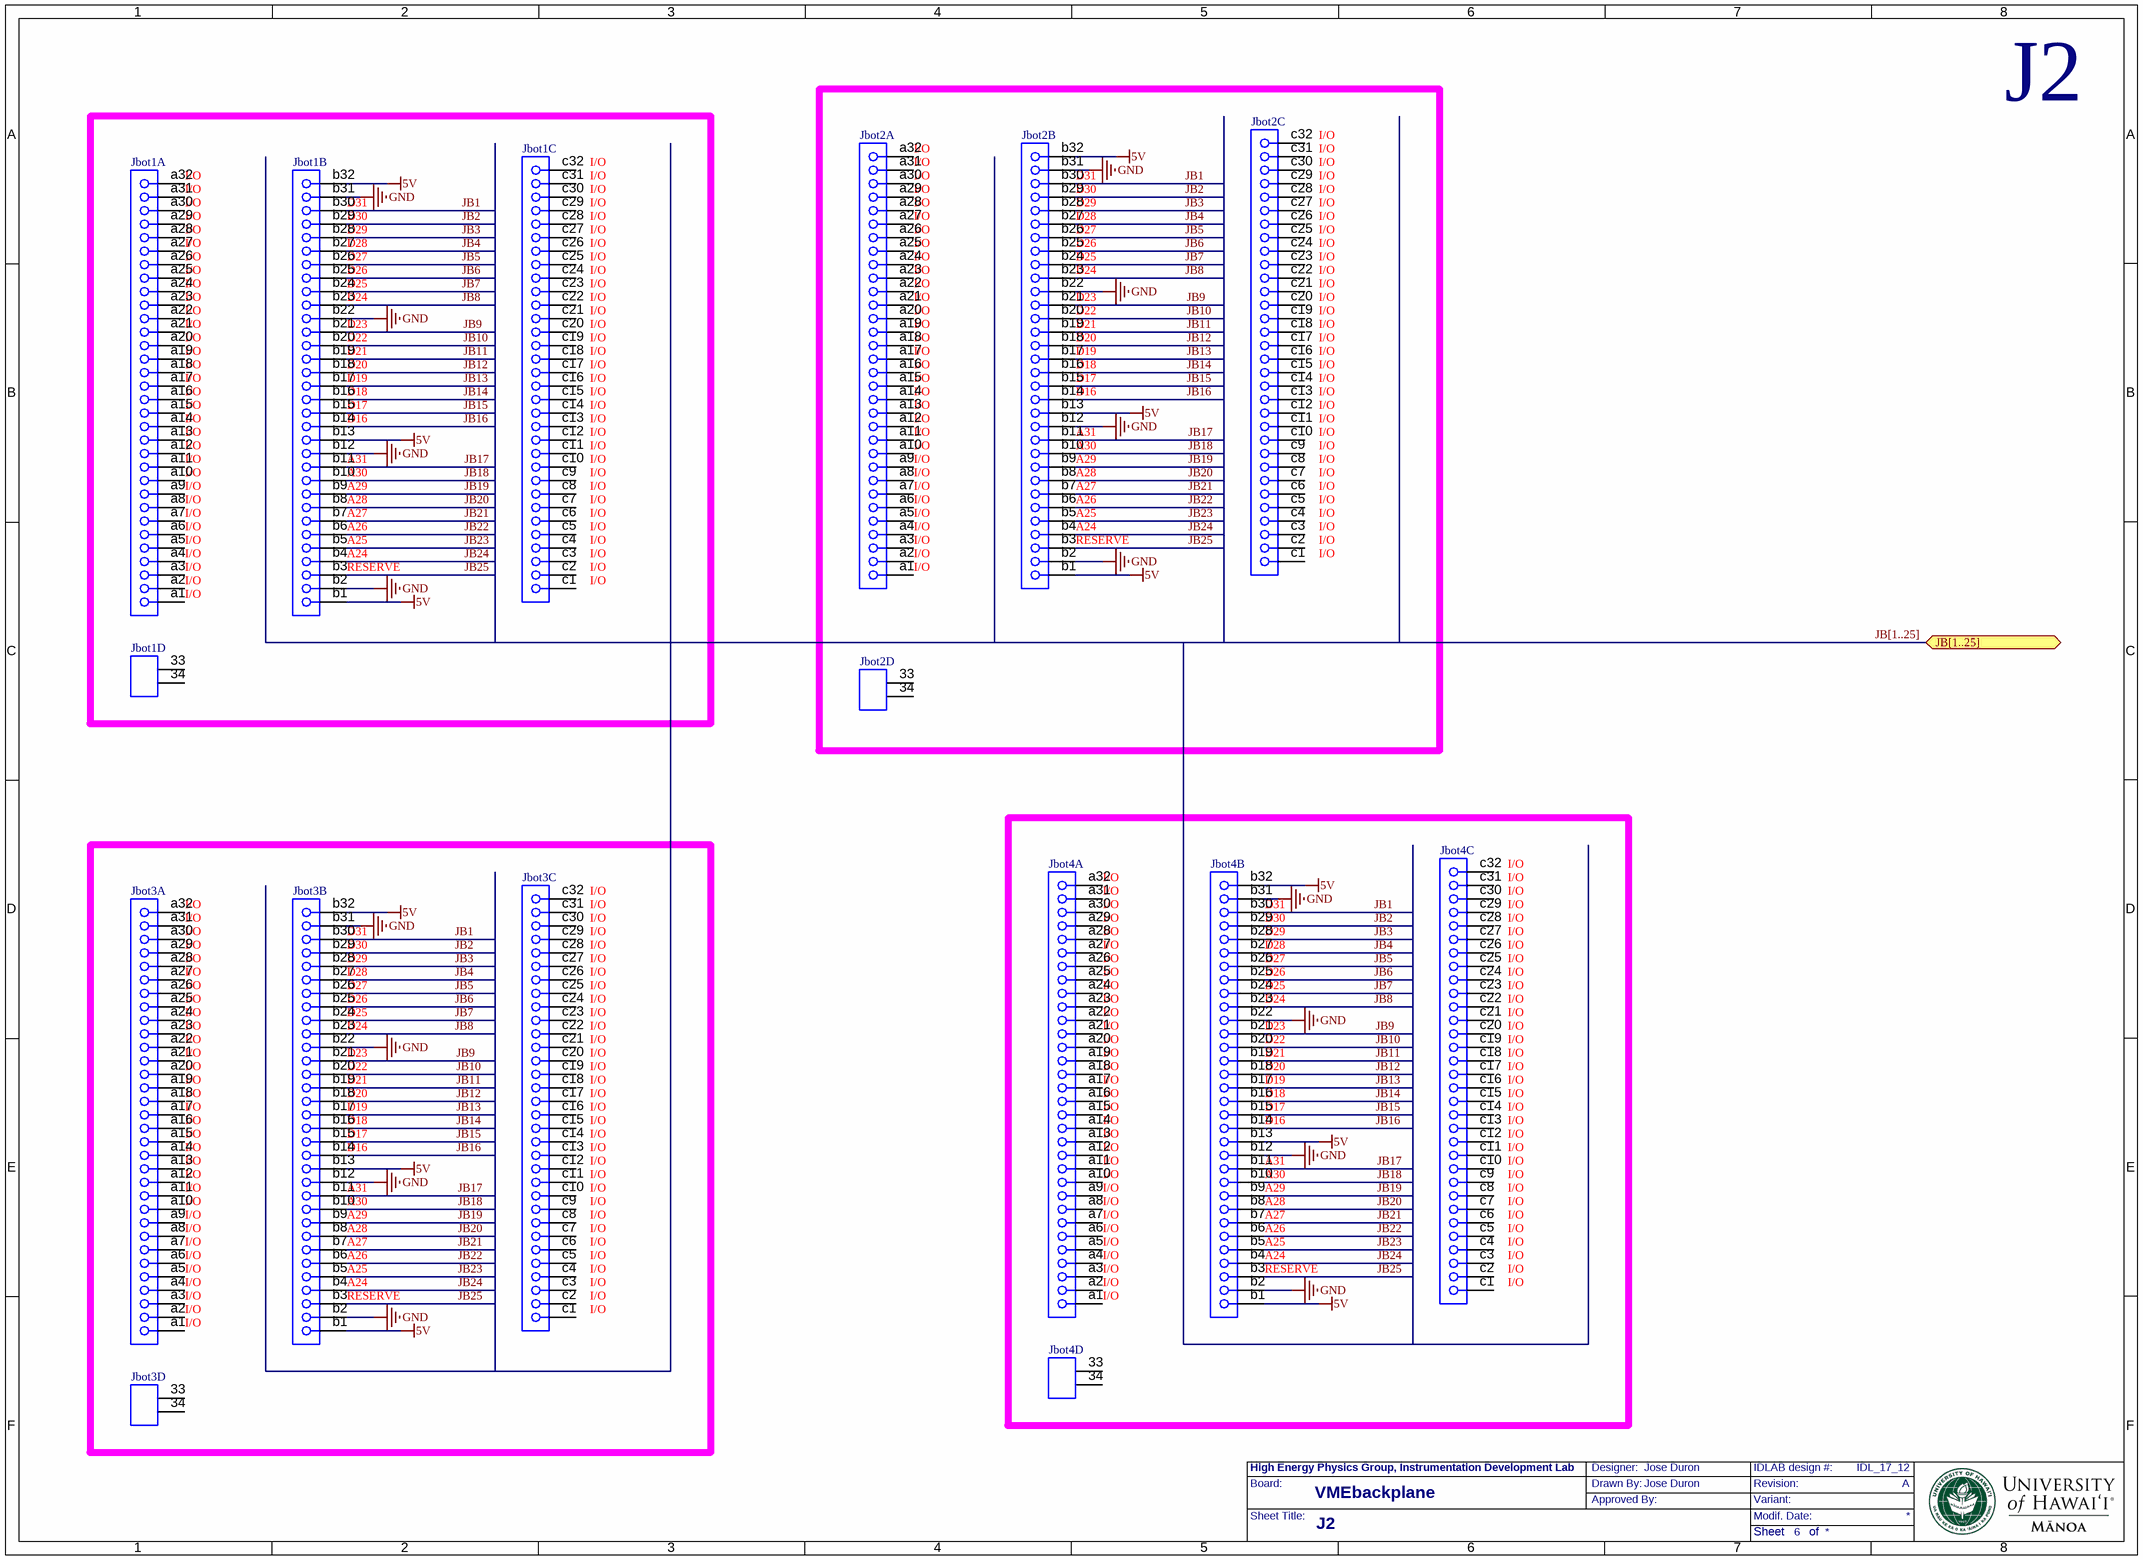
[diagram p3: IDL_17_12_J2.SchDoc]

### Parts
Jbot1  (no value)  [0903296x825]  (parts A,B,C,D of 4)
Jbot2  (no value)  [0903296x825]  (parts A,B,C,D of 4)
Jbot3  (no value)  [0903296x825]  (parts A,B,C,D of 4)
Jbot4  (no value)  [0903296x825]  (parts A,B,C,D of 4)

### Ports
JB[1..25]

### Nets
5V: Jbot1.b1 Jbot1.b13 Jbot1.b32 Jbot2.b1 Jbot2.b13 Jbot2.b32 Jbot3.b1 Jbot3.b13 Jbot3.b32 Jbot4.b1 Jbot4.b13 Jbot4.b32
GND: Jbot1.b2 Jbot1.b12 Jbot1.b22 Jbot1.b31 Jbot2.b2 Jbot2.b12 Jbot2.b22 Jbot2.b31 Jbot3.b2 Jbot3.b12 Jbot3.b22 Jbot3.b31 Jbot4.b2 Jbot4.b12 Jbot4.b22 Jbot4.b31
JB1: Jbot1.b30 Jbot2.b30 Jbot3.b30 Jbot4.b30  [project net JB1_6]
JB2: Jbot1.b29 Jbot2.b29 Jbot3.b29 Jbot4.b29  [project net JB2_6]
JB3: Jbot1.b28 Jbot2.b28 Jbot3.b28 Jbot4.b28  [project net JB3_6]
JB4: Jbot1.b27 Jbot2.b27 Jbot3.b27 Jbot4.b27  [project net JB4_6]
JB5: Jbot1.b26 Jbot2.b26 Jbot3.b26 Jbot4.b26  [project net JB5_6]
JB6: Jbot1.b25 Jbot2.b25 Jbot3.b25 Jbot4.b25  [project net JB6_6]
JB7: Jbot1.b24 Jbot2.b24 Jbot3.b24 Jbot4.b24  [project net JB7_6]
JB8: Jbot1.b23 Jbot2.b23 Jbot3.b23 Jbot4.b23  [project net JB8_6]
JB9: Jbot1.b21 Jbot2.b21 Jbot3.b21 Jbot4.b21  [project net JB9_6]
JB10: Jbot1.b20 Jbot2.b20 Jbot3.b20 Jbot4.b20  [project net JB10_6]
JB11: Jbot1.b19 Jbot2.b19 Jbot3.b19 Jbot4.b19  [project net JB11_6]
JB12: Jbot1.b18 Jbot2.b18 Jbot3.b18 Jbot4.b18  [project net JB12_6]
JB13: Jbot1.b17 Jbot2.b17 Jbot3.b17 Jbot4.b17  [project net JB13_6]
JB14: Jbot1.b16 Jbot2.b16 Jbot3.b16 Jbot4.b16  [project net JB14_6]
JB15: Jbot1.b15 Jbot2.b15 Jbot3.b15 Jbot4.b15  [project net JB15_6]
JB16: Jbot1.b14 Jbot2.b14 Jbot3.b14 Jbot4.b14  [project net JB16_6]
JB17: Jbot1.b11 Jbot2.b11 Jbot3.b11 Jbot4.b11  [project net JB17_6]
JB18: Jbot1.b10 Jbot2.b10 Jbot3.b10 Jbot4.b10  [project net JB18_6]
JB19: Jbot1.b9 Jbot2.b9 Jbot3.b9 Jbot4.b9  [project net JB19_6]
JB20: Jbot1.b8 Jbot2.b8 Jbot3.b8 Jbot4.b8  [project net JB20_6]
JB21: Jbot1.b7 Jbot2.b7 Jbot3.b7 Jbot4.b7  [project net JB21_6]
JB22: Jbot1.b6 Jbot2.b6 Jbot3.b6 Jbot4.b6  [project net JB22_6]
JB23: Jbot1.b5 Jbot2.b5 Jbot3.b5 Jbot4.b5  [project net JB23_6]
JB24: Jbot1.b4 Jbot2.b4 Jbot3.b4 Jbot4.b4  [project net JB24_6]
JB25: Jbot1.b3 Jbot2.b3 Jbot3.b3 Jbot4.b3  [project net JB25_6]

Not connected (* = marked no-connect by the designer): Jbot1 33(MH1) 34(MH2) a1 a2 a3 a4 a5 a6 a7 a8 a9 a10 a11 a12 a13 a14 a15 a16 a17 a18 a19 a20 a21 a22 a23 a24 a25 a26 a27 a28 a29 a30 a31 a32 c1 c2 c3 c4 c5 c6 c7 c8 c9 c10 c11 c12 c13 c14 c15 c16 c17 c18 c19 c20 c21 c22 c23 c24 c25 c26 c27 c28 c29 c30 c31 c32; Jbot2 33(MH1) 34(MH2) a1 a2 a3 a4 a5 a6 a7 a8 a9 a10 a11 a12 a13 a14 a15 a16 a17 a18 a19 a20 a21 a22 a23 a24 a25 a26 a27 a28 a29 a30 a31 a32 c1 c2 c3 c4 c5 c6 c7 c8 c9 c10 c11 c12 c13 c14 c15 c16 c17 c18 c19 c20 c21 c22 c23 c24 c25 c26 c27 c28 c29 c30 c31 c32; Jbot3 33(MH1) 34(MH2) a1 a2 a3 a4 a5 a6 a7 a8 a9 a10 a11 a12 a13 a14 a15 a16 a17 a18 a19 a20 a21 a22 a23 a24 a25 a26 a27 a28 a29 a30 a31 a32 c1 c2 c3 c4 c5 c6 c7 c8 c9 c10 c11 c12 c13 c14 c15 c16 c17 c18 c19 c20 c21 c22 c23 c24 c25 c26 c27 c28 c29 c30 c31 c32; Jbot4 33(MH1) 34(MH2) a1 a2 a3 a4 a5 a6 a7 a8 a9 a10 a11 a12 a13 a14 a15 a16 a17 a18 a19 a20 a21 a22 a23 a24 a25 a26 a27 a28 a29 a30 a31 a32 c1 c2 c3 c4 c5 c6 c7 c8 c9 c10 c11 c12 c13 c14 c15 c16 c17 c18 c19 c20 c21 c22 c23 c24 c25 c26 c27 c28 c29 c30 c31 c32

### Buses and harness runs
bus JB[1..25] = port JB[1..25]

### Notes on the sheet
- (near Jbot1) I/O
- (near Jbot2) I/O
- J2
- (near Jbot1) D31
- (near Jbot1) D30
- (near Jbot1) D29
- (near Jbot2) D31
- (near Jbot2) D30
- (near Jbot2) D29
- (near Jbot2) D28
- (near Jbot2) D27
- (near Jbot1) D28
- (near Jbot1) D27
- (near Jbot1) D26
- (near Jbot1) D25
- (near Jbot1) D24
- (near Jbot2) D26
- (near Jbot2) D25
- (near Jbot2) D24
- (near Jbot2) D23
- (near Jbot1) D23
- (near Jbot1) D22
- (near Jbot1) D21
- (near Jbot1) D20
- (near Jbot2) D22
- (near Jbot2) D21
- (near Jbot2) D20
- (near Jbot2) D19
- (near Jbot2) D18
- (near Jbot1) D19
- (near Jbot1) D18
- (near Jbot1) D17
- (near Jbot1) D16
- (near Jbot2) D17
- (near Jbot2) D16
- (near Jbot2) A31
- (near Jbot1) A31
- (near Jbot1) A30
- (near Jbot1) A29
- (near Jbot1) A28
- (near Jbot2) A30
- (near Jbot2) A29
- (near Jbot2) A28
- (near Jbot2) A27
- (near Jbot2) A26
- (near Jbot1) A27
- (near Jbot1) A26
- (near Jbot1) A25
- (near Jbot1) A24
- (near Jbot1) RESERVE
- (near Jbot2) A25
- (near Jbot2) A24
- (near Jbot2) RESERVE
- (near Jbot3) I/O
- (near Jbot4) I/O
- (near Jbot4) D31
- (near Jbot3) D31
- (near Jbot3) D30
- (near Jbot3) D29
- (near Jbot3) D28
- (near Jbot4) D30
- (near Jbot4) D29
- (near Jbot4) D28
- (near Jbot4) D27
- (near Jbot4) D26
- (near Jbot3) D27
- (near Jbot3) D26
- (near Jbot3) D25
- (near Jbot3) D24
- (near Jbot4) D25
- (near Jbot4) D24
- (near Jbot4) D23
- (near Jbot4) D22
- (near Jbot3) D23
- (near Jbot3) D22
- (near Jbot3) D21
- (near Jbot3) D20
- (near Jbot3) D19
- (near Jbot4) D21
- (near Jbot4) D20
- (near Jbot4) D19
- (near Jbot4) D18
- (near Jbot4) D17
- (near Jbot3) D18
- (near Jbot3) D17
- (near Jbot3) D16
- (near Jbot4) D16
- (near Jbot4) A31
- (near Jbot4) A30
- (near Jbot3) A31
- (near Jbot3) A30
- (near Jbot3) A29
- (near Jbot3) A28
- (near Jbot3) A27
- (near Jbot4) A29
- (near Jbot4) A28
- (near Jbot4) A27
- (near Jbot4) A26
- (near Jbot4) A25
- (near Jbot3) A26
- (near Jbot3) A25
- (near Jbot3) A24
- (near Jbot3) RESERVE
- (near Jbot4) A24
- (near Jbot4) RESERVE

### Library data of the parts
Jbot1-Jbot4 = 09 03 296 2825: as Jtop1 on sheet IDL_17_12_J1

## Sheet IDL_17_12_TerA.SchDoc: Termination A
size 401 x 291 mm; SheetNumber: 7
Used 72 times, as channels IDL_IDL_17_12_VME/IDL_17_12_TerA1, IDL_IDL_17_12_VME/IDL_17_12_TerA2, IDL_IDL_17_12_VME/IDL_17_12_TerA3, IDL_IDL_17_12_VME/IDL_17_12_TerA4, IDL_IDL_17_12_VME/IDL_17_12_TerA5, IDL_IDL_17_12_VME/IDL_17_12_TerA6, IDL_IDL_17_12_VME/IDL_17_12_TerA7, IDL_IDL_17_12_VME/IDL_17_12_TerA8, IDL_IDL_17_12_VME/IDL_17_12_TerA9, IDL_IDL_17_12_VME/IDL_17_12_TerA10, IDL_IDL_17_12_VME/IDL_17_12_TerA11, IDL_IDL_17_12_VME/IDL_17_12_TerA12, IDL_IDL_17_12_VME/IDL_17_12_TerA13, IDL_IDL_17_12_VME/IDL_17_12_TerA14, IDL_IDL_17_12_VME/IDL_17_12_TerA15, IDL_IDL_17_12_VME/IDL_17_12_TerA16, IDL_IDL_17_12_VME/IDL_17_12_TerA17, IDL_IDL_17_12_VME/IDL_17_12_TerA18, IDL_IDL_17_12_VME/IDL_17_12_TerA19, IDL_IDL_17_12_VME/IDL_17_12_TerA20, IDL_IDL_17_12_VME/IDL_17_12_TerA21, IDL_IDL_17_12_VME/IDL_17_12_TerA22, IDL_IDL_17_12_VME/IDL_17_12_TerA23, IDL_IDL_17_12_VME/IDL_17_12_TerA24, IDL_IDL_17_12_VME/IDL_17_12_TerA25, IDL_IDL_17_12_VME/IDL_17_12_TerA26, IDL_IDL_17_12_VME/IDL_17_12_TerA27, IDL_IDL_17_12_VME/IDL_17_12_TerA28, IDL_IDL_17_12_VME/IDL_17_12_TerA29, IDL_IDL_17_12_VME/IDL_17_12_TerA30, IDL_IDL_17_12_VME/IDL_17_12_TerA31, IDL_IDL_17_12_VME/IDL_17_12_TerA32, IDL_IDL_17_12_VME/IDL_17_12_TerA33, IDL_IDL_17_12_VME/IDL_17_12_TerA34, IDL_IDL_17_12_VME/IDL_17_12_TerA35, IDL_IDL_17_12_VME/IDL_17_12_TerA36, IDL_IDL_17_12_VME/IDL_17_12_TerA37, IDL_IDL_17_12_VME/IDL_17_12_TerA38, IDL_IDL_17_12_VME/IDL_17_12_TerA39, IDL_IDL_17_12_VME/IDL_17_12_TerA40, IDL_IDL_17_12_VME/IDL_17_12_TerA41, IDL_IDL_17_12_VME/IDL_17_12_TerA42, IDL_IDL_17_12_VME/IDL_17_12_TerA43, IDL_IDL_17_12_VME/IDL_17_12_TerA44, IDL_IDL_17_12_VME/IDL_17_12_TerA45, IDL_IDL_17_12_VME/IDL_17_12_TerA46, IDL_IDL_17_12_VME/IDL_17_12_TerA47, IDL_IDL_17_12_VME/IDL_17_12_TerA48, IDL_IDL_17_12_VME/IDL_17_12_TerA49, IDL_IDL_17_12_VME/IDL_17_12_TerA50, IDL_IDL_17_12_VME/IDL_17_12_TerA51, IDL_IDL_17_12_VME/IDL_17_12_TerA52, IDL_IDL_17_12_VME/IDL_17_12_TerA53, IDL_IDL_17_12_VME/IDL_17_12_TerA54, IDL_IDL_17_12_VME/IDL_17_12_TerA55, IDL_IDL_17_12_VME/IDL_17_12_TerA56, IDL_IDL_17_12_VME/IDL_17_12_TerA57, IDL_IDL_17_12_VME/IDL_17_12_TerA58, IDL_IDL_17_12_VME/IDL_17_12_TerA59, IDL_IDL_17_12_VME/IDL_17_12_TerA60, IDL_IDL_17_12_VME/IDL_17_12_TerA61, IDL_IDL_17_12_VME/IDL_17_12_TerA62, IDL_IDL_17_12_VME/IDL_17_12_TerA63, IDL_IDL_17_12_VME/IDL_17_12_TerA64, IDL_IDL_17_12_VME/IDL_17_12_TerA65, IDL_IDL_17_12_VME/IDL_17_12_TerA66, IDL_IDL_17_12_VME/IDL_17_12_TerA67, IDL_IDL_17_12_VME/IDL_17_12_TerA68, IDL_IDL_17_12_VME/IDL_17_12_TerA69, IDL_IDL_17_12_VME/IDL_17_12_TerA70, IDL_IDL_17_12_VME/IDL_17_12_TerA71, IDL_IDL_17_12_VME/IDL_17_12_TerA72. Parts and nets are listed once, with the designators drawn on the sheet.
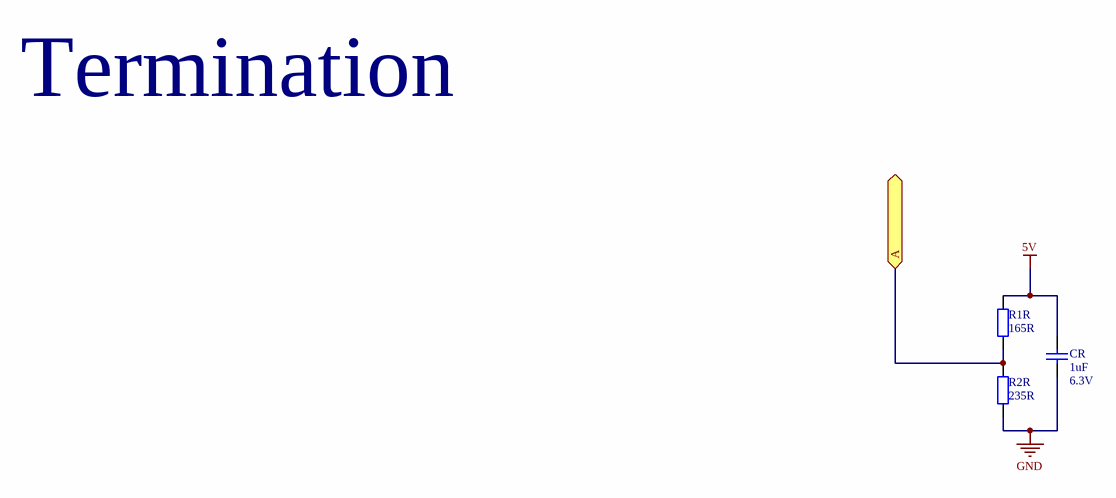
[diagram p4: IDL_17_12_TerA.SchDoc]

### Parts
CR  1uF  Voltage rating: 6.3V  [CC0402N1X]
R1R  165R  [RC0402N1R]
R2R  235R  [RC0402N1R]

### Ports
A

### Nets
5V: CR.2 R1R.2
GND: CR.1 R2R.1
A: R1R.1 R2R.2 ; port A

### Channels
IDL_IDL_17_12_VME/IDL_17_12_TerA1: designators end in _IDL_17_12_TerA1; ports A=A
IDL_IDL_17_12_VME/IDL_17_12_TerA2: designators end in _IDL_17_12_TerA2; ports A=A
IDL_IDL_17_12_VME/IDL_17_12_TerA3: designators end in _IDL_17_12_TerA3; ports A=A
IDL_IDL_17_12_VME/IDL_17_12_TerA4: designators end in _IDL_17_12_TerA4; ports A=A
IDL_IDL_17_12_VME/IDL_17_12_TerA5: designators end in _IDL_17_12_TerA5; ports A=A
IDL_IDL_17_12_VME/IDL_17_12_TerA6: designators end in _IDL_17_12_TerA6; ports A=A
IDL_IDL_17_12_VME/IDL_17_12_TerA7: designators end in _IDL_17_12_TerA7; ports A=A
IDL_IDL_17_12_VME/IDL_17_12_TerA8: designators end in _IDL_17_12_TerA8; ports A=A
IDL_IDL_17_12_VME/IDL_17_12_TerA9: designators end in _IDL_17_12_TerA9; ports A=A
IDL_IDL_17_12_VME/IDL_17_12_TerA10: designators end in _IDL_17_12_TerA10; ports A=A
IDL_IDL_17_12_VME/IDL_17_12_TerA11: designators end in _IDL_17_12_TerA11; ports A=A
IDL_IDL_17_12_VME/IDL_17_12_TerA12: designators end in _IDL_17_12_TerA12; ports A=A
IDL_IDL_17_12_VME/IDL_17_12_TerA13: designators end in _IDL_17_12_TerA13; ports A=A
IDL_IDL_17_12_VME/IDL_17_12_TerA14: designators end in _IDL_17_12_TerA14; ports A=A
IDL_IDL_17_12_VME/IDL_17_12_TerA15: designators end in _IDL_17_12_TerA15; ports A=A
IDL_IDL_17_12_VME/IDL_17_12_TerA16: designators end in _IDL_17_12_TerA16; ports A=A
IDL_IDL_17_12_VME/IDL_17_12_TerA17: designators end in _IDL_17_12_TerA17; ports A=A
IDL_IDL_17_12_VME/IDL_17_12_TerA18: designators end in _IDL_17_12_TerA18; ports A=A
IDL_IDL_17_12_VME/IDL_17_12_TerA19: designators end in _IDL_17_12_TerA19; ports A=A
IDL_IDL_17_12_VME/IDL_17_12_TerA20: designators end in _IDL_17_12_TerA20; ports A=A
IDL_IDL_17_12_VME/IDL_17_12_TerA21: designators end in _IDL_17_12_TerA21; ports A=A
IDL_IDL_17_12_VME/IDL_17_12_TerA22: designators end in _IDL_17_12_TerA22; ports A=A
IDL_IDL_17_12_VME/IDL_17_12_TerA23: designators end in _IDL_17_12_TerA23; ports A=A
IDL_IDL_17_12_VME/IDL_17_12_TerA24: designators end in _IDL_17_12_TerA24; ports A=A
IDL_IDL_17_12_VME/IDL_17_12_TerA25: designators end in _IDL_17_12_TerA25; ports A=A
IDL_IDL_17_12_VME/IDL_17_12_TerA26: designators end in _IDL_17_12_TerA26; ports A=A
IDL_IDL_17_12_VME/IDL_17_12_TerA27: designators end in _IDL_17_12_TerA27; ports A=A
IDL_IDL_17_12_VME/IDL_17_12_TerA28: designators end in _IDL_17_12_TerA28; ports A=A
IDL_IDL_17_12_VME/IDL_17_12_TerA29: designators end in _IDL_17_12_TerA29; ports A=A
IDL_IDL_17_12_VME/IDL_17_12_TerA30: designators end in _IDL_17_12_TerA30; ports A=A
IDL_IDL_17_12_VME/IDL_17_12_TerA31: designators end in _IDL_17_12_TerA31; ports A=A
IDL_IDL_17_12_VME/IDL_17_12_TerA32: designators end in _IDL_17_12_TerA32; ports A=A
IDL_IDL_17_12_VME/IDL_17_12_TerA33: designators end in _IDL_17_12_TerA33; ports A=A
IDL_IDL_17_12_VME/IDL_17_12_TerA34: designators end in _IDL_17_12_TerA34; ports A=A
IDL_IDL_17_12_VME/IDL_17_12_TerA35: designators end in _IDL_17_12_TerA35; ports A=A
IDL_IDL_17_12_VME/IDL_17_12_TerA36: designators end in _IDL_17_12_TerA36; ports A=A
IDL_IDL_17_12_VME/IDL_17_12_TerA37: designators end in _IDL_17_12_TerA37; ports A=A
IDL_IDL_17_12_VME/IDL_17_12_TerA38: designators end in _IDL_17_12_TerA38; ports A=A
IDL_IDL_17_12_VME/IDL_17_12_TerA39: designators end in _IDL_17_12_TerA39; ports A=A
IDL_IDL_17_12_VME/IDL_17_12_TerA40: designators end in _IDL_17_12_TerA40; ports A=A
IDL_IDL_17_12_VME/IDL_17_12_TerA41: designators end in _IDL_17_12_TerA41; ports A=A
IDL_IDL_17_12_VME/IDL_17_12_TerA42: designators end in _IDL_17_12_TerA42; ports A=A
IDL_IDL_17_12_VME/IDL_17_12_TerA43: designators end in _IDL_17_12_TerA43; ports A=A
IDL_IDL_17_12_VME/IDL_17_12_TerA44: designators end in _IDL_17_12_TerA44; ports A=A
IDL_IDL_17_12_VME/IDL_17_12_TerA45: designators end in _IDL_17_12_TerA45; ports A=A
IDL_IDL_17_12_VME/IDL_17_12_TerA46: designators end in _IDL_17_12_TerA46; ports A=A
IDL_IDL_17_12_VME/IDL_17_12_TerA47: designators end in _IDL_17_12_TerA47; ports A=A
IDL_IDL_17_12_VME/IDL_17_12_TerA48: designators end in _IDL_17_12_TerA48; ports A=A
IDL_IDL_17_12_VME/IDL_17_12_TerA49: designators end in _IDL_17_12_TerA49; ports A=A
IDL_IDL_17_12_VME/IDL_17_12_TerA50: designators end in _IDL_17_12_TerA50; ports A=A
IDL_IDL_17_12_VME/IDL_17_12_TerA51: designators end in _IDL_17_12_TerA51; ports A=A
IDL_IDL_17_12_VME/IDL_17_12_TerA52: designators end in _IDL_17_12_TerA52; ports A=A
IDL_IDL_17_12_VME/IDL_17_12_TerA53: designators end in _IDL_17_12_TerA53; ports A=A
IDL_IDL_17_12_VME/IDL_17_12_TerA54: designators end in _IDL_17_12_TerA54; ports A=A
IDL_IDL_17_12_VME/IDL_17_12_TerA55: designators end in _IDL_17_12_TerA55; ports A=A
IDL_IDL_17_12_VME/IDL_17_12_TerA56: designators end in _IDL_17_12_TerA56; ports A=A
IDL_IDL_17_12_VME/IDL_17_12_TerA57: designators end in _IDL_17_12_TerA57; ports A=A
IDL_IDL_17_12_VME/IDL_17_12_TerA58: designators end in _IDL_17_12_TerA58; ports A=A
IDL_IDL_17_12_VME/IDL_17_12_TerA59: designators end in _IDL_17_12_TerA59; ports A=A
IDL_IDL_17_12_VME/IDL_17_12_TerA60: designators end in _IDL_17_12_TerA60; ports A=A
IDL_IDL_17_12_VME/IDL_17_12_TerA61: designators end in _IDL_17_12_TerA61; ports A=A
IDL_IDL_17_12_VME/IDL_17_12_TerA62: designators end in _IDL_17_12_TerA62; ports A=A
IDL_IDL_17_12_VME/IDL_17_12_TerA63: designators end in _IDL_17_12_TerA63; ports A=A
IDL_IDL_17_12_VME/IDL_17_12_TerA64: designators end in _IDL_17_12_TerA64; ports A=A
IDL_IDL_17_12_VME/IDL_17_12_TerA65: designators end in _IDL_17_12_TerA65; ports A=A
IDL_IDL_17_12_VME/IDL_17_12_TerA66: designators end in _IDL_17_12_TerA66; ports A=A
IDL_IDL_17_12_VME/IDL_17_12_TerA67: designators end in _IDL_17_12_TerA67; ports A=A
IDL_IDL_17_12_VME/IDL_17_12_TerA68: designators end in _IDL_17_12_TerA68; ports A=A
IDL_IDL_17_12_VME/IDL_17_12_TerA69: designators end in _IDL_17_12_TerA69; ports A=A
IDL_IDL_17_12_VME/IDL_17_12_TerA70: designators end in _IDL_17_12_TerA70; ports A=A
IDL_IDL_17_12_VME/IDL_17_12_TerA71: designators end in _IDL_17_12_TerA71; ports A=A
IDL_IDL_17_12_VME/IDL_17_12_TerA72: designators end in _IDL_17_12_TerA72; ports A=A

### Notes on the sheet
- Termination

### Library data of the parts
CR = CAPCC0402_2_1.0U_50VX7R: Capacitor chip ceramic 0402 6.3V X7R; Manufacturer: TDK; Manufacturer No: GRM155R70J105KA12D; Tech: SMDR
R1R R2R = RES0402-0-499R-1%100PPM: Chip Resistor 0402 62.5mW 1% 100ppm; Manufacturer: Panasonic; Manufacturer No: ERJ-2RKF4990X; Tech: SMDR

## Sheet IDL_17_12_TerB.SchDoc: Termination B
size 401 x 291 mm; SheetNumber: 8
Used 25 times, as channels IDL_IDL_17_12_VME/IDL_17_12_TerB1, IDL_IDL_17_12_VME/IDL_17_12_TerB2, IDL_IDL_17_12_VME/IDL_17_12_TerB3, IDL_IDL_17_12_VME/IDL_17_12_TerB4, IDL_IDL_17_12_VME/IDL_17_12_TerB5, IDL_IDL_17_12_VME/IDL_17_12_TerB6, IDL_IDL_17_12_VME/IDL_17_12_TerB7, IDL_IDL_17_12_VME/IDL_17_12_TerB8, IDL_IDL_17_12_VME/IDL_17_12_TerB9, IDL_IDL_17_12_VME/IDL_17_12_TerB10, IDL_IDL_17_12_VME/IDL_17_12_TerB11, IDL_IDL_17_12_VME/IDL_17_12_TerB12, IDL_IDL_17_12_VME/IDL_17_12_TerB13, IDL_IDL_17_12_VME/IDL_17_12_TerB14, IDL_IDL_17_12_VME/IDL_17_12_TerB15, IDL_IDL_17_12_VME/IDL_17_12_TerB16, IDL_IDL_17_12_VME/IDL_17_12_TerB17, IDL_IDL_17_12_VME/IDL_17_12_TerB18, IDL_IDL_17_12_VME/IDL_17_12_TerB19, IDL_IDL_17_12_VME/IDL_17_12_TerB20, IDL_IDL_17_12_VME/IDL_17_12_TerB21, IDL_IDL_17_12_VME/IDL_17_12_TerB22, IDL_IDL_17_12_VME/IDL_17_12_TerB23, IDL_IDL_17_12_VME/IDL_17_12_TerB24, IDL_IDL_17_12_VME/IDL_17_12_TerB25. Parts and nets are listed once, with the designators drawn on the sheet.
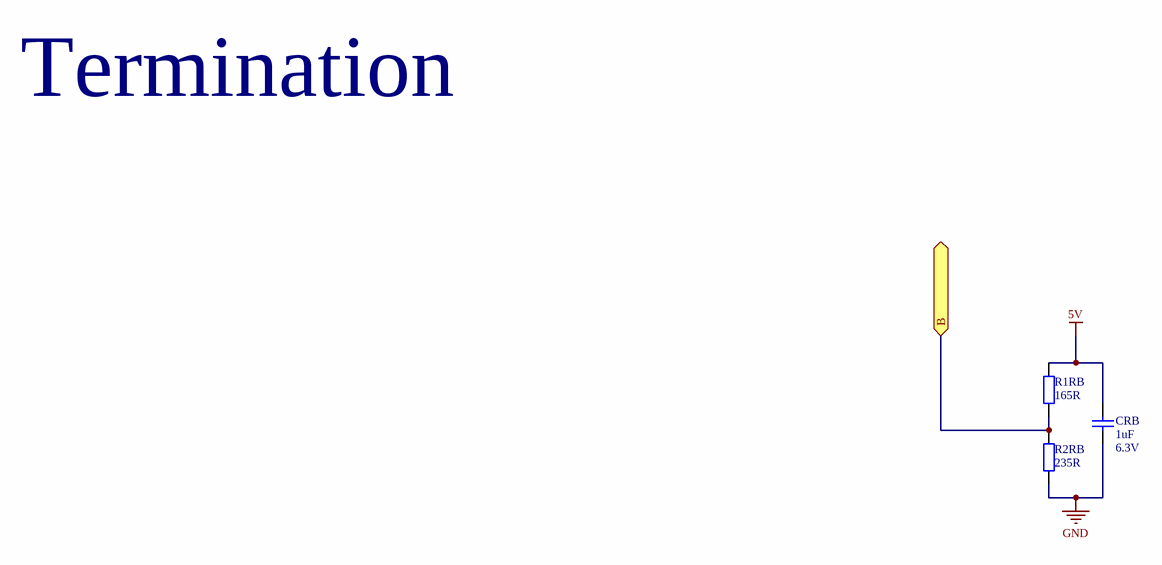
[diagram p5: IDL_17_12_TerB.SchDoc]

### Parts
CRB  1uF  Voltage rating: 6.3V  [CC0402N1X]
R1RB  165R  [RC0402N1R]
R2RB  235R  [RC0402N1R]

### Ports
B

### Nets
5V: CRB.2 R1RB.2
GND: CRB.1 R2RB.1
B: R1RB.1 R2RB.2 ; port B

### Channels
IDL_IDL_17_12_VME/IDL_17_12_TerB1: designators end in _IDL_17_12_TerB1; ports B=B
IDL_IDL_17_12_VME/IDL_17_12_TerB2: designators end in _IDL_17_12_TerB2; ports B=B
IDL_IDL_17_12_VME/IDL_17_12_TerB3: designators end in _IDL_17_12_TerB3; ports B=B
IDL_IDL_17_12_VME/IDL_17_12_TerB4: designators end in _IDL_17_12_TerB4; ports B=B
IDL_IDL_17_12_VME/IDL_17_12_TerB5: designators end in _IDL_17_12_TerB5; ports B=B
IDL_IDL_17_12_VME/IDL_17_12_TerB6: designators end in _IDL_17_12_TerB6; ports B=B
IDL_IDL_17_12_VME/IDL_17_12_TerB7: designators end in _IDL_17_12_TerB7; ports B=B
IDL_IDL_17_12_VME/IDL_17_12_TerB8: designators end in _IDL_17_12_TerB8; ports B=B
IDL_IDL_17_12_VME/IDL_17_12_TerB9: designators end in _IDL_17_12_TerB9; ports B=B
IDL_IDL_17_12_VME/IDL_17_12_TerB10: designators end in _IDL_17_12_TerB10; ports B=B
IDL_IDL_17_12_VME/IDL_17_12_TerB11: designators end in _IDL_17_12_TerB11; ports B=B
IDL_IDL_17_12_VME/IDL_17_12_TerB12: designators end in _IDL_17_12_TerB12; ports B=B
IDL_IDL_17_12_VME/IDL_17_12_TerB13: designators end in _IDL_17_12_TerB13; ports B=B
IDL_IDL_17_12_VME/IDL_17_12_TerB14: designators end in _IDL_17_12_TerB14; ports B=B
IDL_IDL_17_12_VME/IDL_17_12_TerB15: designators end in _IDL_17_12_TerB15; ports B=B
IDL_IDL_17_12_VME/IDL_17_12_TerB16: designators end in _IDL_17_12_TerB16; ports B=B
IDL_IDL_17_12_VME/IDL_17_12_TerB17: designators end in _IDL_17_12_TerB17; ports B=B
IDL_IDL_17_12_VME/IDL_17_12_TerB18: designators end in _IDL_17_12_TerB18; ports B=B
IDL_IDL_17_12_VME/IDL_17_12_TerB19: designators end in _IDL_17_12_TerB19; ports B=B
IDL_IDL_17_12_VME/IDL_17_12_TerB20: designators end in _IDL_17_12_TerB20; ports B=B
IDL_IDL_17_12_VME/IDL_17_12_TerB21: designators end in _IDL_17_12_TerB21; ports B=B
IDL_IDL_17_12_VME/IDL_17_12_TerB22: designators end in _IDL_17_12_TerB22; ports B=B
IDL_IDL_17_12_VME/IDL_17_12_TerB23: designators end in _IDL_17_12_TerB23; ports B=B
IDL_IDL_17_12_VME/IDL_17_12_TerB24: designators end in _IDL_17_12_TerB24; ports B=B
IDL_IDL_17_12_VME/IDL_17_12_TerB25: designators end in _IDL_17_12_TerB25; ports B=B

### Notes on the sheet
- Termination

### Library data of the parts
CRB = CAPCC0402_2_1.0U_50VX7R: as CR on sheet IDL_17_12_TerA
R1RB R2RB = RES0402-0-499R-1%100PPM: as R1R on sheet IDL_17_12_TerA

## Sheet IDL_17_12_J0.SchDoc: J0
size 401 x 291 mm; SheetNumber: 4
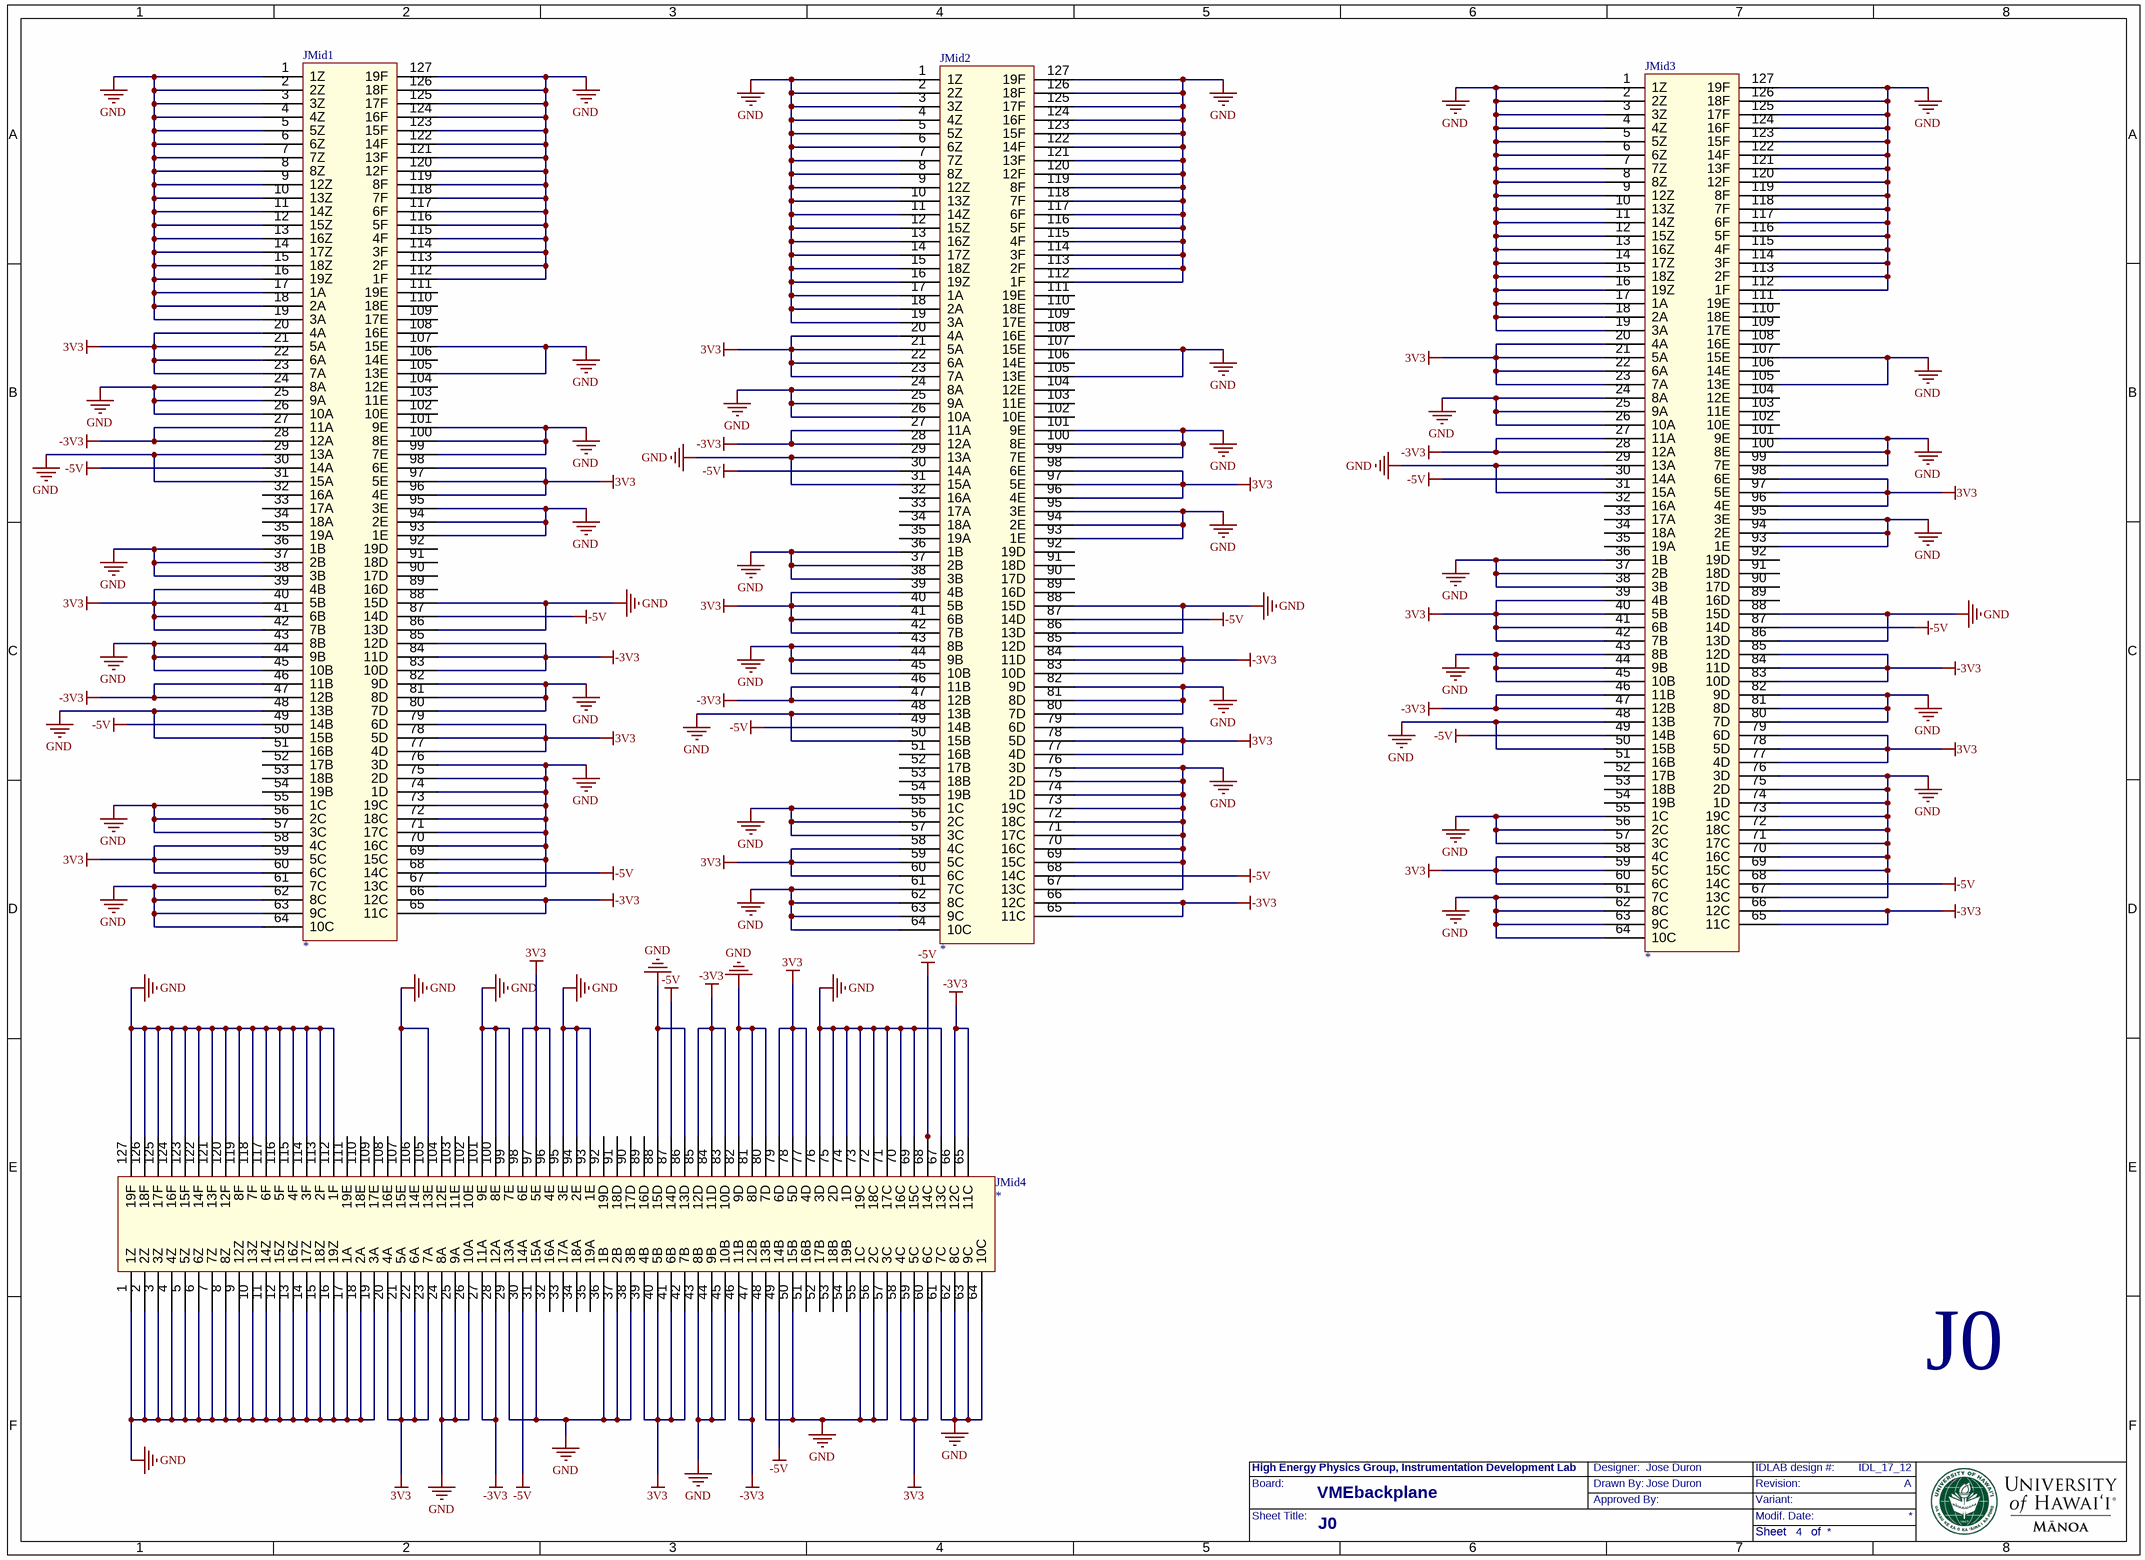
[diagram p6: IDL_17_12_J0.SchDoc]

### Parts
JMid1  *  [127-Pin Conncector]
JMid2  *  [127-Pin Conncector]
JMid3  *  [127-Pin Conncector]
JMid4  *  [127-Pin Conncector]

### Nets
3V3: JMid1.20(4A) JMid1.21(5A) JMid1.22(6A) JMid1.23(7A) JMid1.39(4B) JMid1.40(5B) JMid1.41(6B) JMid1.42(7B) JMid1.58(4C) JMid1.59(5C) JMid1.60(6C) JMid1.77(4D) JMid1.78(5D) JMid1.79(6D) JMid1.96(4E) JMid1.97(5E) JMid1.98(6E) JMid2.20(4A) JMid2.21(5A) JMid2.22(6A) JMid2.23(7A) JMid2.39(4B) JMid2.40(5B) JMid2.41(6B) JMid2.42(7B) JMid2.58(4C) JMid2.59(5C) JMid2.60(6C) JMid2.77(4D) JMid2.78(5D) JMid2.79(6D) JMid2.96(4E) JMid2.97(5E) JMid2.98(6E) JMid3.20(4A) JMid3.21(5A) JMid3.22(6A) JMid3.23(7A) JMid3.39(4B) JMid3.40(5B) JMid3.41(6B) JMid3.42(7B) JMid3.58(4C) JMid3.59(5C) JMid3.60(6C) JMid3.77(4D) JMid3.78(5D) JMid3.79(6D) JMid3.96(4E) JMid3.97(5E) JMid3.98(6E) JMid4.20(4A) JMid4.21(5A) JMid4.22(6A) JMid4.23(7A) JMid4.39(4B) JMid4.40(5B) JMid4.41(6B) JMid4.42(7B) JMid4.58(4C) JMid4.59(5C) JMid4.60(6C) JMid4.77(4D) JMid4.78(5D) JMid4.79(6D) JMid4.96(4E) JMid4.97(5E) JMid4.98(6E)
-3V3: JMid1.27(11A) JMid1.28(12A) JMid1.46(11B) JMid1.47(12B) JMid1.65(11C) JMid1.66(12C) JMid1.83(10D) JMid1.84(11D) JMid1.85(12D) JMid2.27(11A) JMid2.28(12A) JMid2.46(11B) JMid2.47(12B) JMid2.65(11C) JMid2.66(12C) JMid2.83(10D) JMid2.84(11D) JMid2.85(12D) JMid3.27(11A) JMid3.28(12A) JMid3.46(11B) JMid3.47(12B) JMid3.65(11C) JMid3.66(12C) JMid3.83(10D) JMid3.84(11D) JMid3.85(12D) JMid4.27(11A) JMid4.28(12A) JMid4.46(11B) JMid4.47(12B) JMid4.65(11C) JMid4.66(12C) JMid4.83(10D) JMid4.84(11D) JMid4.85(12D)
-5V: JMid1.30(14A) JMid1.49(14B) JMid1.68(14C) JMid1.87(14D) JMid2.30(14A) JMid2.49(14B) JMid2.68(14C) JMid2.87(14D) JMid3.30(14A) JMid3.49(14B) JMid3.68(14C) JMid3.87(14D) JMid4.30(14A) JMid4.49(14B) JMid4.68(14C) JMid4.87(14D)
GND: JMid1.1(1Z) JMid1.2(2Z) JMid1.3(3Z) JMid1.4(4Z) JMid1.5(5Z) JMid1.6(6Z) JMid1.7(7Z) JMid1.8(8Z) JMid1.9(12Z) JMid1.10(13Z) JMid1.11(14Z) JMid1.12(15Z) JMid1.13(16Z) JMid1.14(17Z) JMid1.15(18Z) JMid1.16(19Z) JMid1.17(1A) JMid1.18(2A) JMid1.19(3A) JMid1.24(8A) JMid1.25(9A) JMid1.26(10A) JMid1.29(13A) JMid1.31(15A) JMid1.36(1B) JMid1.37(2B) JMid1.38(3B) JMid1.43(8B) JMid1.44(9B) JMid1.45(10B) JMid1.48(13B) JMid1.50(15B) JMid1.55(1C) JMid1.56(2C) JMid1.57(3C) JMid1.61(7C) JMid1.62(8C) JMid1.63(9C) JMid1.64(10C) JMid1.67(13C) JMid1.69(15C) JMid1.70(16C) JMid1.71(17C) JMid1.72(18C) JMid1.73(19C) JMid1.74(1D) JMid1.75(2D) JMid1.76(3D) JMid1.80(7D) JMid1.81(8D) JMid1.82(9D) JMid1.86(13D) JMid1.88(15D) JMid1.93(1E) JMid1.94(2E) JMid1.95(3E) JMid1.99(7E) JMid1.100(8E) JMid1.101(9E) JMid1.105(13E) JMid1.107(15E) JMid1.112(1F) JMid1.113(2F) JMid1.114(3F) JMid1.115(4F) JMid1.116(5F) JMid1.117(6F) JMid1.118(7F) JMid1.119(8F) JMid1.120(12F) JMid1.121(13F) JMid1.122(14F) JMid1.123(15F) JMid1.124(16F) JMid1.125(17F) JMid1.126(18F) JMid1.127(19F) JMid2.1(1Z) JMid2.2(2Z) JMid2.3(3Z) JMid2.4(4Z) JMid2.5(5Z) JMid2.6(6Z) JMid2.7(7Z) JMid2.8(8Z) JMid2.9(12Z) JMid2.10(13Z) JMid2.11(14Z) JMid2.12(15Z) JMid2.13(16Z) JMid2.14(17Z) JMid2.15(18Z) JMid2.16(19Z) JMid2.17(1A) JMid2.18(2A) JMid2.19(3A) JMid2.24(8A) JMid2.25(9A) JMid2.26(10A) JMid2.29(13A) JMid2.31(15A) JMid2.36(1B) JMid2.37(2B) JMid2.38(3B) JMid2.43(8B) JMid2.44(9B) JMid2.45(10B) JMid2.48(13B) JMid2.50(15B) JMid2.55(1C) JMid2.56(2C) JMid2.57(3C) JMid2.61(7C) JMid2.62(8C) JMid2.63(9C) JMid2.64(10C) JMid2.67(13C) JMid2.69(15C) JMid2.70(16C) JMid2.71(17C) JMid2.72(18C) JMid2.73(19C) JMid2.74(1D) JMid2.75(2D) JMid2.76(3D) JMid2.80(7D) JMid2.81(8D) JMid2.82(9D) JMid2.86(13D) JMid2.88(15D) JMid2.93(1E) JMid2.94(2E) JMid2.95(3E) JMid2.99(7E) JMid2.100(8E) JMid2.101(9E) JMid2.105(13E) JMid2.107(15E) JMid2.112(1F) JMid2.113(2F) JMid2.114(3F) JMid2.115(4F) JMid2.116(5F) JMid2.117(6F) JMid2.118(7F) JMid2.119(8F) JMid2.120(12F) JMid2.121(13F) JMid2.122(14F) JMid2.123(15F) JMid2.124(16F) JMid2.125(17F) JMid2.126(18F) JMid2.127(19F) JMid3.1(1Z) JMid3.2(2Z) JMid3.3(3Z) JMid3.4(4Z) JMid3.5(5Z) JMid3.6(6Z) JMid3.7(7Z) JMid3.8(8Z) JMid3.9(12Z) JMid3.10(13Z) JMid3.11(14Z) JMid3.12(15Z) JMid3.13(16Z) JMid3.14(17Z) JMid3.15(18Z) JMid3.16(19Z) JMid3.17(1A) JMid3.18(2A) JMid3.19(3A) JMid3.24(8A) JMid3.25(9A) JMid3.26(10A) JMid3.29(13A) JMid3.31(15A) JMid3.36(1B) JMid3.37(2B) JMid3.38(3B) JMid3.43(8B) JMid3.44(9B) JMid3.45(10B) JMid3.48(13B) JMid3.50(15B) JMid3.55(1C) JMid3.56(2C) JMid3.57(3C) JMid3.61(7C) JMid3.62(8C) JMid3.63(9C) JMid3.64(10C) JMid3.67(13C) JMid3.69(15C) JMid3.70(16C) JMid3.71(17C) JMid3.72(18C) JMid3.73(19C) JMid3.74(1D) JMid3.75(2D) JMid3.76(3D) JMid3.80(7D) JMid3.81(8D) JMid3.82(9D) JMid3.86(13D) JMid3.88(15D) JMid3.93(1E) JMid3.94(2E) JMid3.95(3E) JMid3.99(7E) JMid3.100(8E) JMid3.101(9E) JMid3.105(13E) JMid3.107(15E) JMid3.112(1F) JMid3.113(2F) JMid3.114(3F) JMid3.115(4F) JMid3.116(5F) JMid3.117(6F) JMid3.118(7F) JMid3.119(8F) JMid3.120(12F) JMid3.121(13F) JMid3.122(14F) JMid3.123(15F) JMid3.124(16F) JMid3.125(17F) JMid3.126(18F) JMid3.127(19F) JMid4.1(1Z) JMid4.2(2Z) JMid4.3(3Z) JMid4.4(4Z) JMid4.5(5Z) JMid4.6(6Z) JMid4.7(7Z) JMid4.8(8Z) JMid4.9(12Z) JMid4.10(13Z) JMid4.11(14Z) JMid4.12(15Z) JMid4.13(16Z) JMid4.14(17Z) JMid4.15(18Z) JMid4.16(19Z) JMid4.17(1A) JMid4.18(2A) JMid4.19(3A) JMid4.24(8A) JMid4.25(9A) JMid4.26(10A) JMid4.29(13A) JMid4.31(15A) JMid4.36(1B) JMid4.37(2B) JMid4.38(3B) JMid4.43(8B) JMid4.44(9B) JMid4.45(10B) JMid4.48(13B) JMid4.50(15B) JMid4.55(1C) JMid4.56(2C) JMid4.57(3C) JMid4.61(7C) JMid4.62(8C) JMid4.63(9C) JMid4.64(10C) JMid4.67(13C) JMid4.69(15C) JMid4.70(16C) JMid4.71(17C) JMid4.72(18C) JMid4.73(19C) JMid4.74(1D) JMid4.75(2D) JMid4.76(3D) JMid4.80(7D) JMid4.81(8D) JMid4.82(9D) JMid4.86(13D) JMid4.88(15D) JMid4.93(1E) JMid4.94(2E) JMid4.95(3E) JMid4.99(7E) JMid4.100(8E) JMid4.101(9E) JMid4.105(13E) JMid4.107(15E) JMid4.112(1F) JMid4.113(2F) JMid4.114(3F) JMid4.115(4F) JMid4.116(5F) JMid4.117(6F) JMid4.118(7F) JMid4.119(8F) JMid4.120(12F) JMid4.121(13F) JMid4.122(14F) JMid4.123(15F) JMid4.124(16F) JMid4.125(17F) JMid4.126(18F) JMid4.127(19F)

Not connected (* = marked no-connect by the designer): JMid1 32(16A) 33(17A) 34(18A) 35(19A) 51(16B) 52(17B) 53(18B) 54(19B) 89(16D) 90(17D) 91(18D) 92(19D) 102(10E) 103(11E) 104(12E) 106(14E) 108(16E) 109(17E) 110(18E) 111(19E); JMid2 32(16A) 33(17A) 34(18A) 35(19A) 51(16B) 52(17B) 53(18B) 54(19B) 89(16D) 90(17D) 91(18D) 92(19D) 102(10E) 103(11E) 104(12E) 106(14E) 108(16E) 109(17E) 110(18E) 111(19E); JMid3 32(16A) 33(17A) 34(18A) 35(19A) 51(16B) 52(17B) 53(18B) 54(19B) 89(16D) 90(17D) 91(18D) 92(19D) 102(10E) 103(11E) 104(12E) 106(14E) 108(16E) 109(17E) 110(18E) 111(19E); JMid4 32(16A) 33(17A) 34(18A) 35(19A) 51(16B) 52(17B) 53(18B) 54(19B) 89(16D) 90(17D) 91(18D) 92(19D) 102(10E) 103(11E) 104(12E) 106(14E) 108(16E) 109(17E) 110(18E) 111(19E)

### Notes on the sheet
- J0

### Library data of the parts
JMid1-JMid4 = 127-pin connector: Part No.: 17131271201; Tech: THDW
